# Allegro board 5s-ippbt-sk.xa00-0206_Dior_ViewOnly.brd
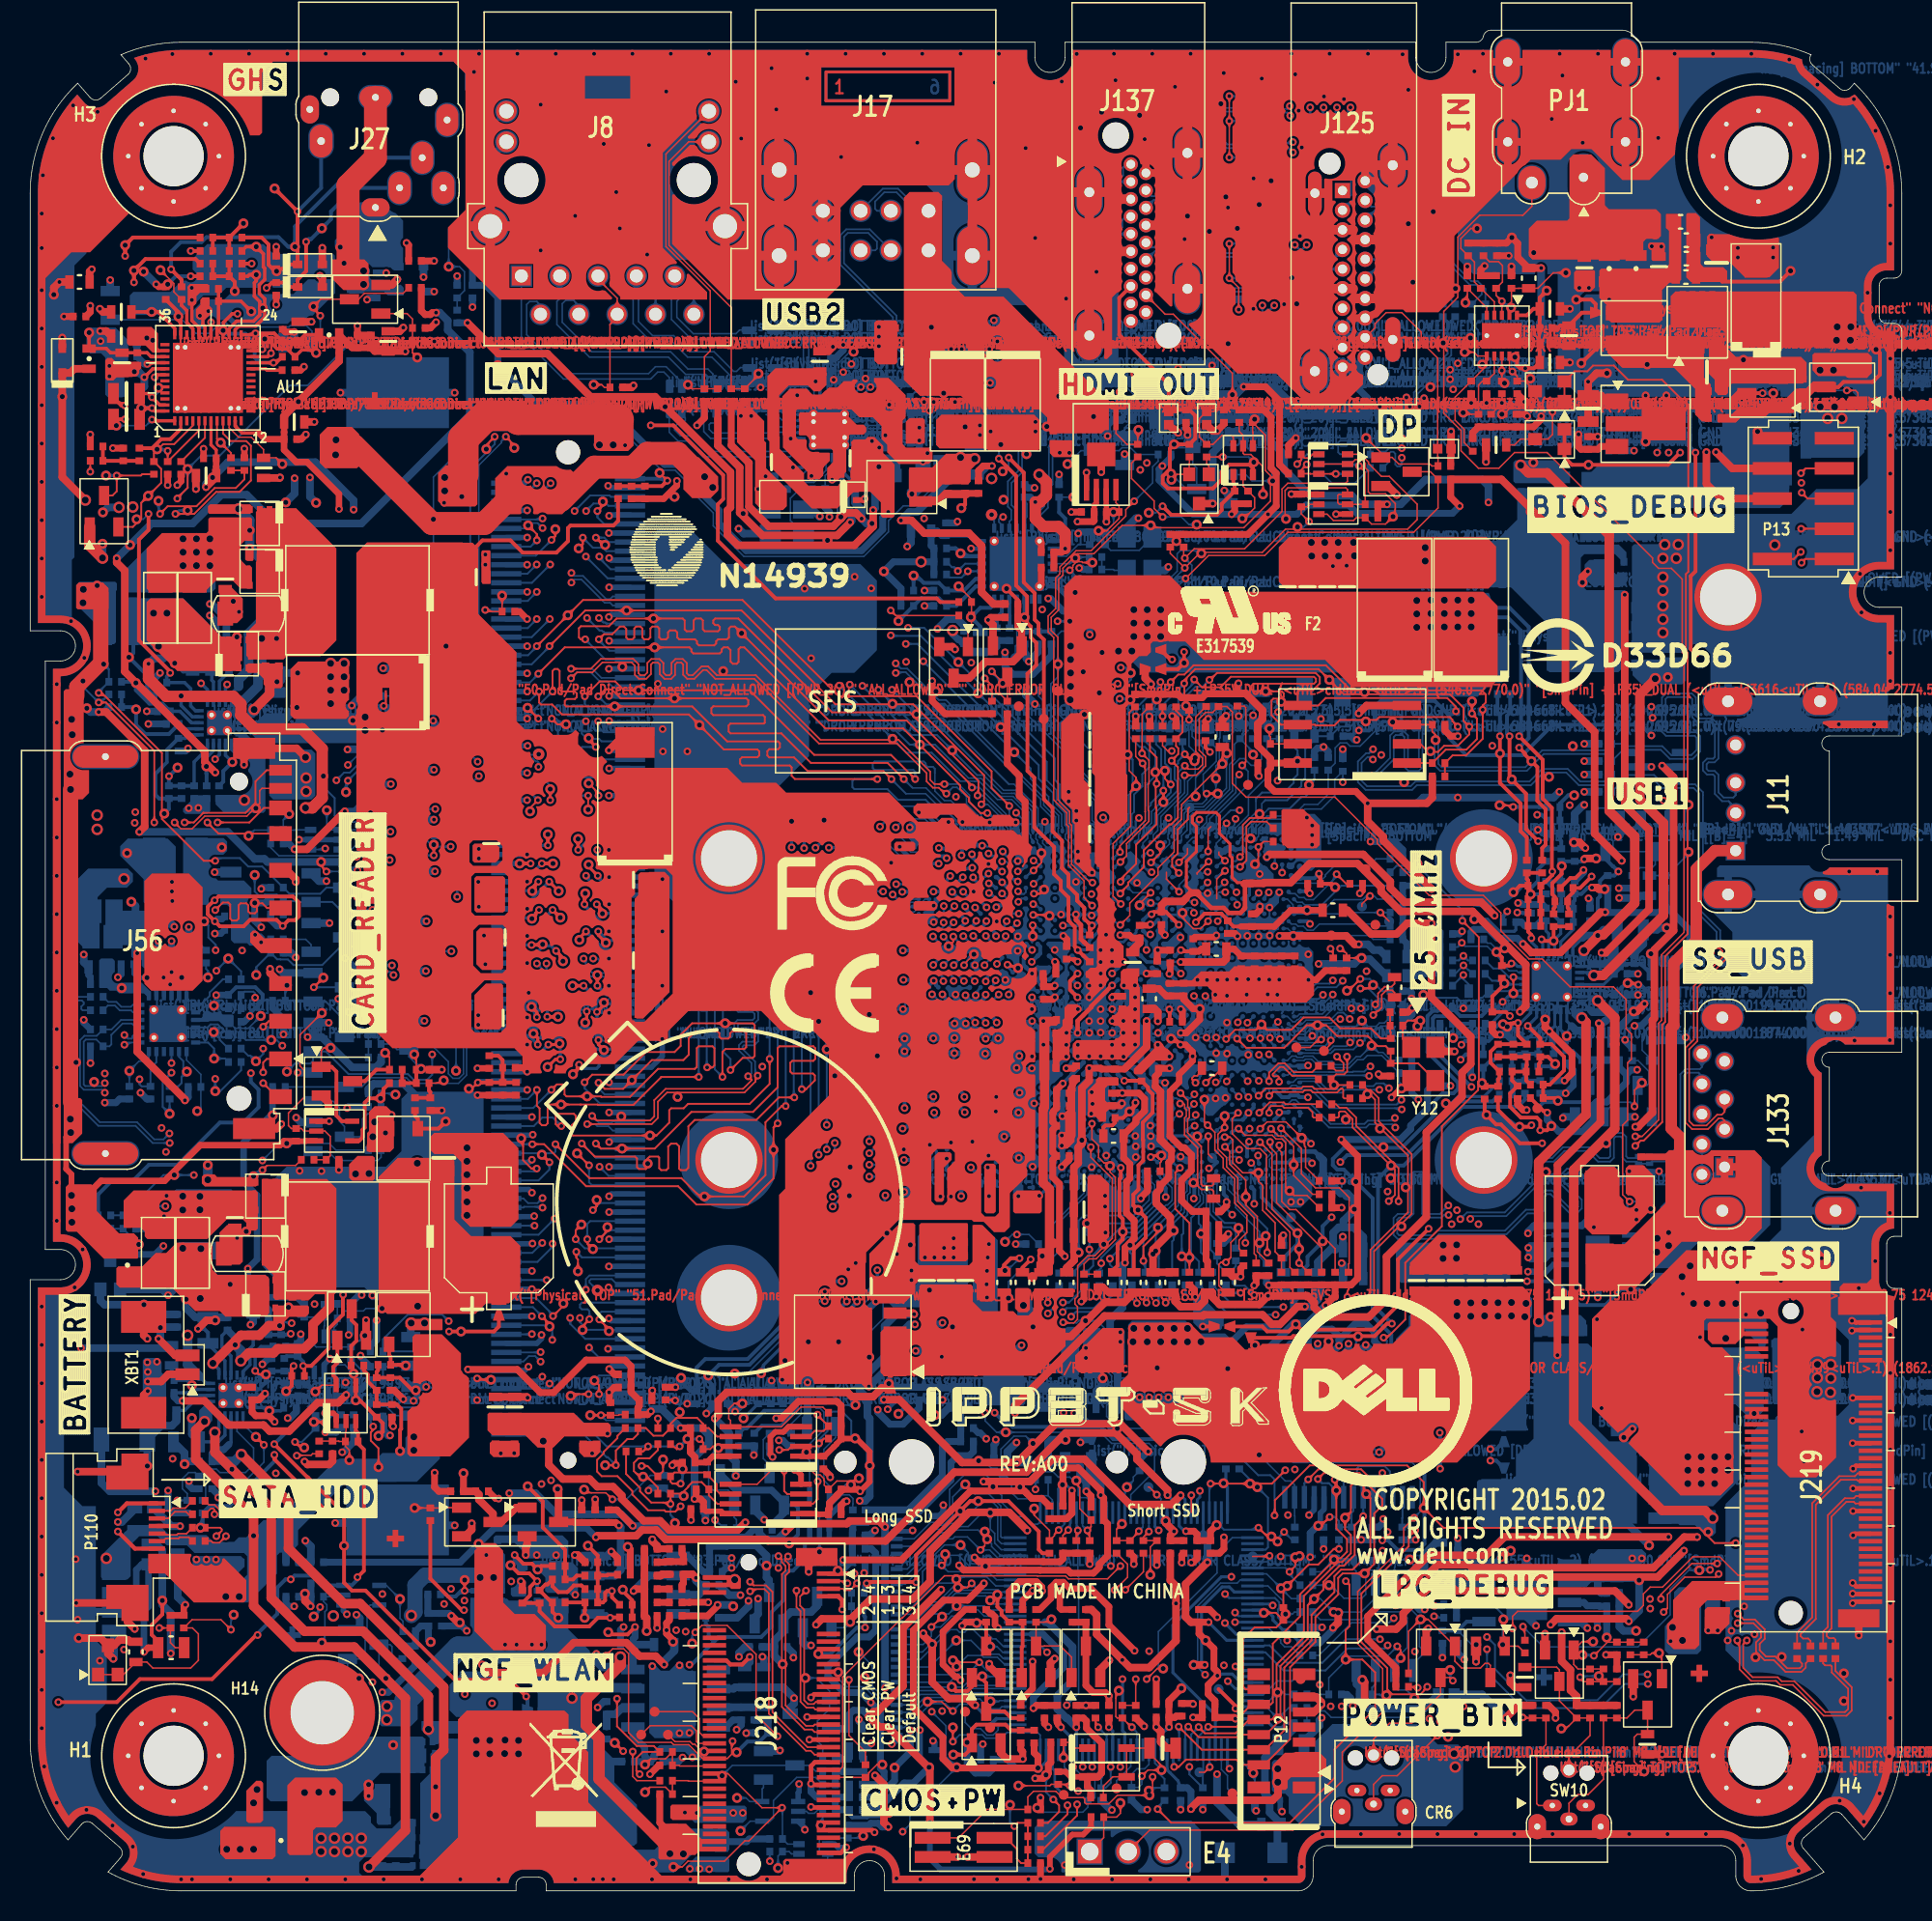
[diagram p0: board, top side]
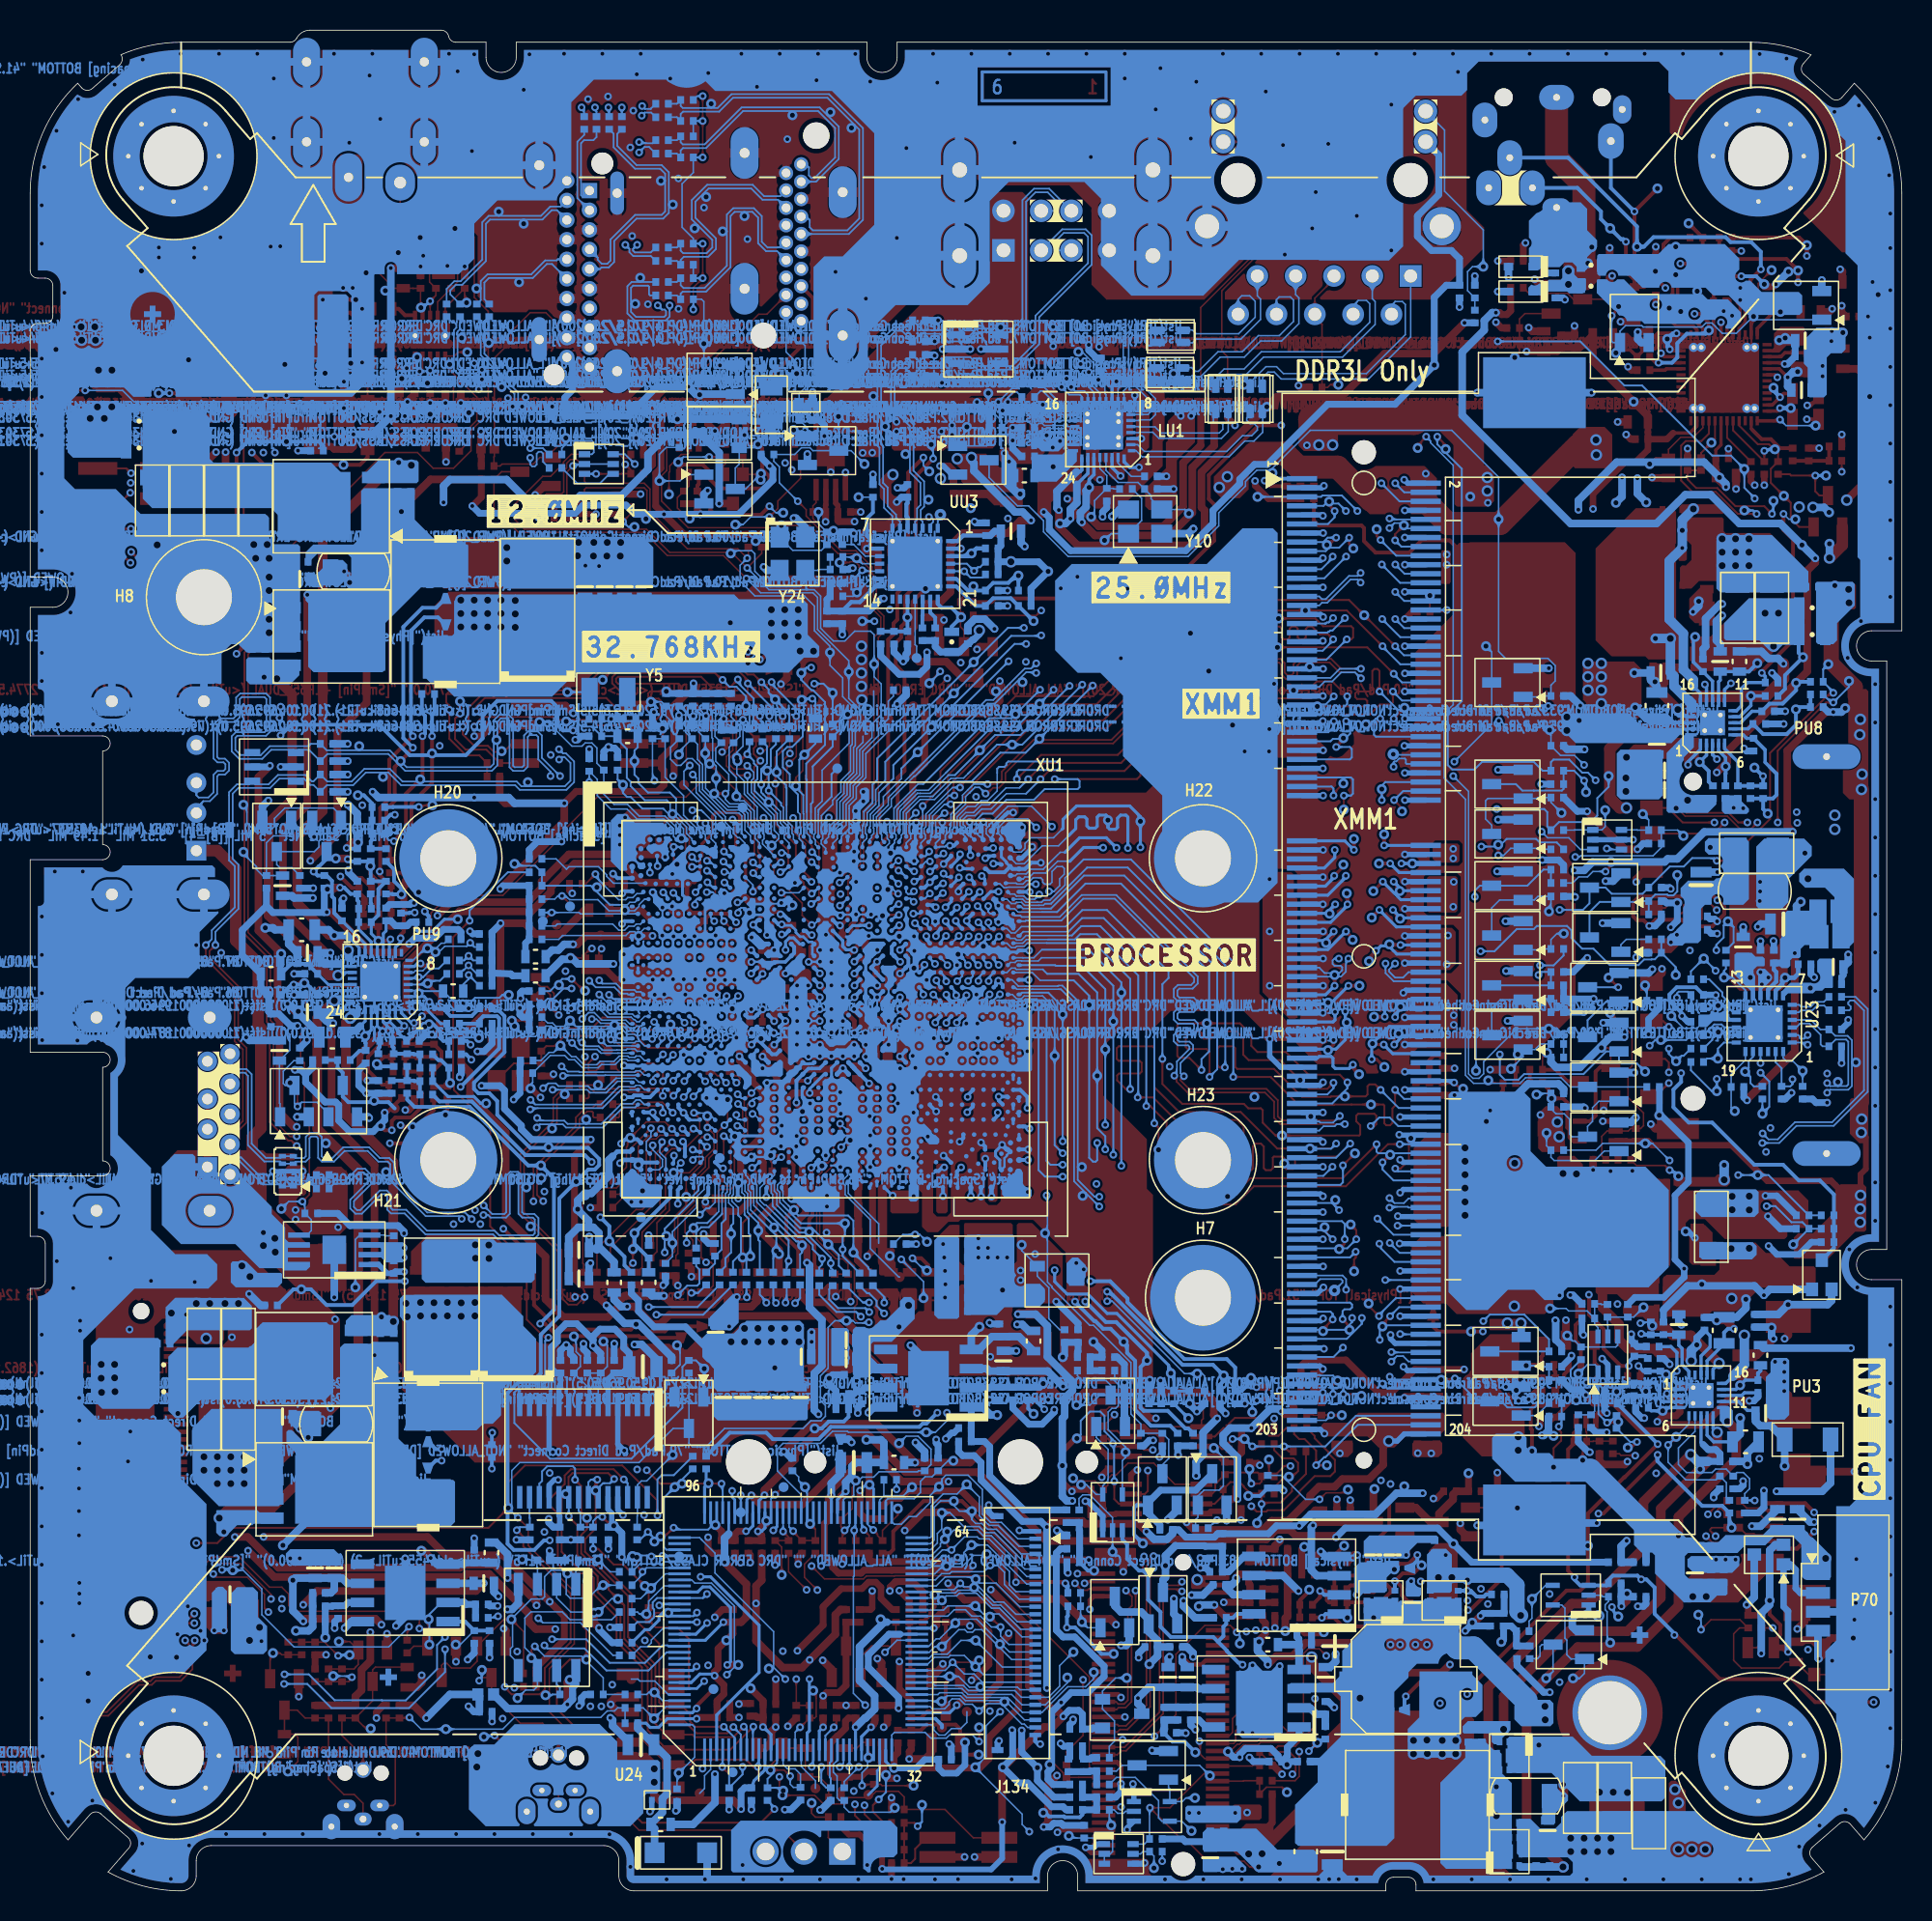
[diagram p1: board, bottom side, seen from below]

Outline 124 x 123.3 mm; copper layers: TOP, VCC, IN1, IN2, GND, BOTTOM. Coordinates in mm from the lower left corner of the outline.
Outline path: 0,112.5 0,83.5 2,83.5 arc(3,82.5) 2,81.5 1,81.5 1,42.5 2,42.5 arc(3,41.5) 2,40.5 0,40.5 0,10 arc(0.65,6.46) 2.51,3.38 3.41,4.42 arc(3.75,4.59) 4.11,4.47 5.93,2.89 arc(6.1,2.55) 5.97,2.19 5.16,1.25 arc(7.5,0.32) 10,0 32.19,0 32.19,0.4 arc(32.33,0.75) 32.69,0.9 33.69,0.9 arc(34.04,0.75) 34.19,0.4 34.19,0 54.6,0 54.6,1 arc(55.6,2) 56.6,1 56.6,0 84,0 arc(84.71,0.29) 85,1 85,2 arc(85.29,2.71) 86,3 112,3 arc(112.71,2.71) 113,2 113,1 arc(113.29,0.29) 114,0 arc(116.5,0.32) 118.84,1.25 117.47,2.83 arc(117.35,3.19) 117.52,3.53 119.33,5.11 arc(119.69,5.23) 120.03,5.06 121.49,3.38 arc(123.35,6.46) 124,10 124,39.92 123.5,39.92 arc(123.15,40.07) 123,40.42 123,42.87 arc(123.15,43.23) 123.5,43.37 124,43.37 124,47.37 119.2,47.37 arc(118.7,47.87) 119.2,48.37 119.2,54.57 arc(118.7,55.07) 119.2,55.57 124,55.57 124,68.33 119.2,68.33 arc(118.7,68.83) 119.2,69.33 119.2,75.53 arc(118.7,76.03) 119.2,76.53 124,76.53 124,85.06 122.5,85.06 arc(121.5,86.06) 122.5,87.06 124,87.06 124,103.37 arc(123.85,103.72) 123.5,103.87 123,103.87 arc(122.65,104.02) 122.5,104.37 122.5,106.37 arc(122.65,106.72) 123,106.87 123.5,106.87 arc(123.85,107.02) 124,107.37 124,112.5 arc(123.18,116.47) 120.85,119.78 120.59,119.48 arc(120.25,119.31) 119.89,119.43 118.07,121.01 arc(117.9,121.32) 117.99,121.67 arc(116.04,122.29) 114,122.5 106.76,122.5 arc(106.52,122.58) 106.35,122.77 arc(105.98,123.16) 105.46,123.3 96.77,123.3 arc(96.45,123.19) 96.28,122.9 arc(96.12,122.62) 95.82,122.5 93.8,122.5 93.8,121.5 arc(92.8,120.5) 91.8,121.5 91.8,122.5 68.56,122.5 68.56,121.5 arc(67.56,120.5) 66.56,121.5 66.56,122.5 10,122.5 arc(7.96,122.29) 6.01,121.67 6.53,121.07 arc(6.65,120.71) 6.48,120.37 4.67,118.79 arc(4.31,118.67) 3.97,118.84 3.15,119.78 arc(0.82,116.47) 0,112.5

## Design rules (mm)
net group HDMI: nets HDMI_TMDS_DATA2_N HDMI_TXN2
net group PCIE_WLAN: nets PCIE_TXP1_WLAN WLAN_PE1_TXP1

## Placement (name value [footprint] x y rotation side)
AC1  -  [MX_C0805_SMALL_T02]  6.38 99.22 180 top
AC2  -  [MX_C0805_SMALL_T02]  6.38 97.51 180 top
AC3  -  [MX_C0402_SMALL_T01]  16.3 107.91 270 top
AC4  -  [MX_C0402_SMALL_T01]  16.3 106.16 90 top
AC5  -  [MX_C0402_SMALL_T01]  22.95 105.98 90 bottom
AC6  -  [MX_C0402_SMALL_T01]  22.95 107.63 90 bottom
AC7  -  [MX_C0402_SMALL_T01]  25.75 103.56 180 top
AC38  -  [MX_C0603_SMALL_T01]  17.49 97.34 0 top
AC39  -  [MX_C0402_SMALL_T01]  17.24 96.2 180 top
AC40  -  [MX_C0603_SMALL_T01]  11.65 93.79 180 top
AC41  -  [MX_C0402_SMALL_T01]  11.9 94.93 0 top
AC42  -  [MX_C0603_SMALL_T01]  6.04 104.63 180 top
AC43  -  [MX_C0402_SMALL_T01]  14.19 94.55 270 top
AC44  -  [MX_C0402_SMALL_T01]  10 94.29 90 top
AC45  -  [MX_C0402_SMALL_T01]  9.11 94.29 90 top
AC46  -  [MX_C0603_SMALL_T01]  15.46 94.29 270 top
AC48  -  [MX_C0603_SMALL_T01]  6.09 101.26 270 top
AC49  -  [MX_C0402_SMALL_T01]  7.1 101.51 90 top
AC50  -  [MX_C0402_SMALL_T01]  3.27 104.33 180 top
AC51  -  [MX_C0402_SMALL_T01]  17.12 101.66 0 top
AC52  -  [MX_C0402_SMALL_T01]  25.49 108.01 0 top
AC53  -  [MX_C0402_SMALL_T01]  21.68 102.68 270 top
AC54  -  [MX_C0603_SMALL_T01]  23.72 102.68 90 top
AC55  -  [MX_C0402_SMALL_T01]  22.57 102.68 270 top
AC56  -  [MX_C0603_SMALL_T01]  17.75 103.31 90 top
AC57  -  [MX_C0402_SMALL_T01]  16.73 103.06 270 top
AC58  -  [MX_C0603_SMALL_T01]  6.04 103.03 180 top
AC59  -  [MX_C0603_SMALL_T01]  6.65 99.45 180 bottom
AC60  -  [MX_C0603_SMALL_T01]  6.4 102.73 180 bottom
AC61  -  [MX_C0402_SMALL_T01]  6.65 101.69 0 bottom
AC62  -  [MX_C0402_SMALL_T01]  17.11 100.77 180 top
AC63  -  [MX_C0402_SMALL_T01]  6.16 95.18 90 top
AD1  -  [MX_SOD523_PHILIPS]  18.53 107.78 0 top
AD2  -  [MX_SOD523_PHILIPS]  18.53 106.28 0 top
AD3  -  [MX_SOD523_PHILIPS]  25.24 105.98 0 bottom
AD4  -  [MX_SOD523_PHILIPS]  25.24 107.63 0 bottom
AQ1  -  [MX_SOT23_H43]  6.34 105.06 180 bottom
AQ2  -  [MX_SOT23_H43]  17.72 103.64 270 bottom
AQ3  -  [MX_SOT23]  22.19 105.47 0 top
AR1  -  [MX_R0402_SMALL_T01]  13.3 94.55 90 top
AR3  -  [MX_R0402_SMALL_T01]  10.03 105.88 90 top
AR5  -  [MX_R0402_SMALL_T01]  12.06 106.16 180 top
AR6  -  [MX_R0402_SMALL]  13.61 109.56 0 top
AR7  -  [MX_R0402_SMALL]  13.61 107.83 0 top
AR8  -  [MX_R0402_SMALL_T01]  25.49 106.23 180 top
AR10  -  [MX_R0402_SMALL_T01]  25.75 102.68 180 top
AR36  -  [MX_R0402_SMALL_T01]  12.06 105.34 180 top
AR37  -  [MX_R0603_SMALL_T01]  3.27 106.61 0 top
AR38  -  [MX_R0402_SMALL_T01]  8.98 105.88 90 top
AU1  -  [MX_QFN_48P_16_S236_PAD_R_8V]  11.78 100.26 0 top
C1  -  [MX_C0402_SMALL]  6.57 43.87 180 bottom
C2  -  [MX_C0402_SMALL_T01]  20.59 31.12 90 bottom
C3  -  [MX_C0402_SMALL_T01]  20.77 37.93 180 bottom
C4  -  [MX_C0402_SMALL_T01]  70.2 89.63 270 bottom
C5  -  [MX_C0402_SMALL_T01]  70.58 87.56 0 bottom
C6  -  [MX_C0402_SMALL_T01]  85.82 51.24 0 top
C7  -  [MX_C0402_SMALL_T01]  85.82 52.13 0 top
C8  -  [MX_C0402_SMALL_T01]  85.77 53.78 180 top
C9  -  [MX_C0402_SMALL_T01]  85.77 54.67 180 top
C10  -  [MX_C0402_SMALL]  64.48 70.42 270 top
C11  -  [MX_C0402_SMALL]  59.53 70.93 270 top
C12  -  [MX_C0402_SMALL]  58.89 65.72 90 top
C13  -  [MX_C0402_SMALL]  63.09 45.27 180 top
C14  -  [MX_C0402_SMALL_T01]  68.67 62.16 270 top
C15  -  [MX_C0402_SMALL_T01]  83.02 42.35 270 bottom
C16  -  [MX_C0402_SMALL_T01]  67.53 56.83 180 top
C17  -  [MX_C0402_SMALL_T01]  67.53 55.43 180 top
C18  -  [MX_C0402_SMALL_T01]  67.53 54.54 180 top
C19  -  [MX_C0402_SMALL_T01]  68.42 57.72 180 top
C20  -  [MX_C0402_SMALL_T01]  78.33 44.13 180 top
C21  -  [MX_C0402_SMALL_T01]  78.33 42.35 180 top
C22  -  [MX_C0402_SMALL_T01]  82.01 61.53 90 top
C23  -  [MX_C0402_SMALL_T01]  82.9 61.53 90 top
C24  -  [MX_C0402_SMALL_T01]  83.79 61.53 90 top
C25  -  [MX_C0402_SMALL_T01]  81.12 61.53 90 top
C26  -  [MX_C0402_SMALL_T01]  80.23 61.53 90 top
C27  -  [MX_C0402_SMALL_T01]  67.15 59.5 90 top
C28  -  [MX_C0402_SMALL_T01]  73.5 63.56 90 top
C30  -  [MX_C0402_SMALL_T01]  75.53 61.91 270 top
C31  -  [MX_C0402_SMALL_T01]  60.67 47.68 0 top
C32  -  [MX_C0402_SMALL_T01]  64.99 45.27 180 top
C33  -  [MX_C0402_SMALL_T01]  58.26 68.77 270 top
C34  -  [MX_C0402_SMALL_T01]  63.09 47.05 180 top
C35  -  [MX_C0402_SMALL_T01]  60.67 46.8 0 top
C36  -  [MX_C0402_SMALL_T01]  62.58 70.42 270 top
C37  -  [MX_C0402_SMALL_T01]  71.85 54.03 90 top
C38  -  [MX_C0402_SMALL_T01]  74.67 61.2 270 top
C39  -  [MX_C0603_SMALL_T02]  69.82 43.43 0 top
C40  -  [MX_C0603_SMALL_T02]  69.82 45.14 0 top
C41  -  [MX_C0603_SMALL_T02]  69.82 46.92 0 top
C42  -  [MX_C0402_SMALL_T01]  75.91 57.59 180 top
C43  -  [MX_C0402_SMALL_T01]  85.06 66.73 0 top
C44  -  [MX_C0402_SMALL_T01]  74.77 54.92 270 top
C45  -  [MX_C0402_SMALL_T01]  79.34 63.86 90 top
C46  -  [MX_C0402_SMALL_T01]  80.95 64.32 270 top
C47  -  [MX_C0402_SMALL_T01]  73.63 54.09 270 top
C48  -  [MX_C0402_SMALL_T01]  62.32 42.99 180 top
C49  -  [MX_C0402_SMALL_T01]  62.32 42.1 180 top
C50  -  [MX_C0402_SMALL_T01]  58.77 43.87 0 top
C51  -  [MX_C0402_SMALL_T01]  62.32 39.3 180 bottom
C52  -  [MX_C0402_SMALL_T01]  62.32 43.87 180 top
C53  -  [MX_C0402_SMALL_T01]  62.32 38.41 180 bottom
C54  -  [MX_C0402_SMALL_T01]  62.32 40.19 180 bottom
C55  -  [MX_C0402_SMALL_T01]  62.32 41.97 180 bottom
C56  -  [MX_C0603_SMALL_T01]  75.53 32.7 270 bottom
C57  -  [MX_C0603_SMALL_T01]  78.07 32.7 270 bottom
C58  -  [MX_C0603_SMALL_T01]  76.8 32.7 270 bottom
C59  -  [MX_C0603_SMALL_T01]  73.04 61.53 90 top
C60  -  [MX_C0603_SMALL_T01]  72.99 32.7 270 bottom
C61  -  [MX_C0603_SMALL_T01]  74.26 32.7 270 bottom
C62  -  [MX_C0402_SMALL_T01]  75.53 59.72 270 top
C63  -  [MX_C0402_SMALL_T01]  76.42 59.72 270 top
C64  -  [MX_C0603_SMALL_T02]  87.65 42.47 180 bottom
C65  -  [MX_C0603_SMALL_T01]  87.65 40.57 180 bottom
C66  -  [MX_C0402_SMALL_T01]  74.44 46.8 0 top
C67  -  [MX_C0402_SMALL_T01]  77.87 76.64 270 top
C68  -  [MX_C0402_SMALL_T01]  74.95 64.45 90 top
C69  -  [MX_C0402_SMALL_T01]  71.67 52.43 90 top
C70  -  [MX_C0402_SMALL_T01]  71.46 51.22 0 top
C71  -  [MX_C0402_SMALL_T01]  68.42 52.87 180 top
C72  -  [MX_C0402_SMALL_T01]  68.42 52 180 top
C73  -  [MX_C0402_SMALL_T01]  68.42 50.69 180 top
C74  -  [MX_C0402_SMALL_T01]  68.42 48.7 180 top
C75  -  [MX_C0402_SMALL_T01]  69.3 54.25 90 top
C76  -  [MX_C0402_SMALL_T01]  72.36 58.86 270 top
C77  -  [MX_C0402_SMALL_T01]  72.61 34.73 0 top
C78  -  [MX_C0402_SMALL_T01]  72.61 35.62 0 top
C79  -  [MX_C0603_SMALL_T02]  70.2 73.72 180 top
C80  -  [MX_C0603_SMALL_T02]  70.2 76.26 180 top
C81  -  [MX_C0603_SMALL_T02]  70.2 77.53 180 top
C82  -  [MX_C0603_SMALL_T01]  70.2 74.99 180 top
C83  -  [MX_C0402_SMALL]  70.48 69 0 top
C84  -  [MX_C0402_SMALL]  70.48 68.11 0 top
C85  -  [MX_C0603_SMALL_T01]  70.2 72.45 180 top
C86  -  [MX_C0603_SMALL_T01]  70.2 70.04 180 top
C89  -  [MX_C0402_SMALL]  30.42 54.92 90 top
C149  -  [MX_C0402_SMALL_T01]  66.51 5.39 180 top
C150  -  [MX_C0402_SMALL_T01]  66.51 1.84 180 top
C151  -  [MX_C0402_SMALL_T01]  54.15 93.89 0 top
C152  -  [MX_C0402_SMALL_T01]  48.86 95.69 0 top
C153  -  [MX_C0603_SMALL_T01]  52.32 101.36 90 top
C154  -  [MX_C0402_SMALL]  55.03 96.35 270 top
C155  -  [MX_C0402_SMALL_T01]  52.67 95.44 270 top
C156  -  [MX_C0402_SMALL_T01]  57.88 96.2 180 top
C157  -  [MX_C0402_SMALL_T01]  51.17 98.05 90 top
C158  -  [MX_C0402_SMALL_T01]  51.17 96.28 270 top
C159  -  [MX_C0402_SMALL_T01]  57.88 97.09 180 top
C160  -  [MX_C0402_SMALL_T01]  57.88 95.06 180 bottom
C161  -  [MX_C0402_SMALL_T01]  57.88 99.88 180 bottom
C162  -  [MX_C0402_SMALL_T01]  57.88 98.99 180 bottom
C163  -  [MX_C0402_SMALL_T01]  57.88 97.98 180 bottom
C174  -  [MX_C0402_SMALL_T01]  7.23 95.18 270 top
C240  -  [MX_C0402_SMALL]  6.57 44.76 180 bottom
C245  -  [MX_C0402_SMALL_T01]  13.3 64.58 0 bottom
C246  -  [MX_C0805_SMALL_T02]  13.3 66.64 90 bottom
C248  -  [MX_C0402_SMALL]  13.56 59.37 0 bottom
C249  -  [MX_C0402_SMALL_T01]  13.3 63.69 0 bottom
C250  -  [MX_C0402_SMALL_T01]  4.41 55.97 0 bottom
C251  -  [MX_C0402_SMALL_T01]  4.41 57.08 0 bottom
C252  -  [MX_C0603_SMALL_T01]  4.54 61.22 180 bottom
C253  -  [MX_C0402_SMALL_T01]  4.41 60.08 0 bottom
C254  -  [MX_C0402_SMALL]  13.56 57.59 180 bottom
C255  -  [MX_C0603_SMALL_T01]  10.51 62.54 90 bottom
C256  -  [MX_C0402_SMALL_T01]  9.36 61.91 270 bottom
C257  -  [MX_C0402_SMALL_T01]  8.48 61.91 270 bottom
C260  -  [MX_C0805_SMALL_T02]  83.53 9.69 0 bottom
C261  -  [MX_C0402_SMALL_T01]  78.07 12.38 0 top
C262  -  [MX_C0402_SMALL_T01]  78.07 11.49 0 top
C263  -  [MX_C0402_SMALL_T01]  77.44 18.22 270 top
C264  -  [MX_C0402_SMALL_T01]  69.31 11.87 270 top
C265  -  [MX_C0805_SMALL_T02]  69.44 28.38 0 bottom
C266  -  [MX_C0402_SMALL_T01]  70.71 25.46 180 top
C267  -  [MX_C0402_SMALL_T01]  76.22 6.41 90 bottom
C268  -  [MX_C0402_SMALL_T01]  75.02 12.38 0 top
C269  -  [MX_C0402_SMALL]  76.29 12 270 top
C272  -  [MX_C0402_SMALL_T01]  93.82 11.87 0 bottom
C302  -  [MX_C0402_SMALL_T01]  7.97 52.89 270 bottom
C307  -  [MX_C0603_SMALL_T01]  49.12 94.67 180 top
C308  -  [MX_C0603_SMALL_T01]  54.32 94.93 180 top
C941134  -  [MX_C0402_SMALL_T01]  78.33 45.02 180 top
C941135  -  [MX_C0402_SMALL_T01]  78.33 43.24 180 top
C941136  -  [MX_C0402_SMALL_T01]  67.53 60.77 180 top
C941137  -  [MX_C0402_SMALL_T01]  77.06 62.67 270 top
C941138  -  [MX_C0402_SMALL_T01]  62.32 42.86 180 bottom
C941139  -  [MX_C0402_SMALL_T01]  62.32 41.08 180 bottom
C941140  -  [MX_C0402_SMALL_T01]  39.84 58.1 180 top
C941141  -  [MX_C0402_SMALL_T01]  39.84 59.88 180 top
C941156  -  [MX_C0402_SMALL_T01]  67.78 96.33 90 top
C941162  -  [MX_C0402_SMALL_T01]  82.77 76.77 270 bottom
C941163  -  [MX_C0402_SMALL_T01]  75.91 76.77 270 top
CB1  -  [MX_C0805_SMALL]  83.41 34.73 0 bottom
CB2  -  [MX_C0402_SMALL_T01]  87.55 23.68 90 bottom
CB3  -  [MX_C0402_SMALL_T01]  90.9 23.68 90 bottom
CB6  -  [MX_C0402_SMALL_T01]  99.92 41.33 90 bottom
CB7  -  [MX_C0402_SMALL_T01]  107.66 41.08 90 bottom
CB10  -  [MX_C0603_SMALL]  107.15 9.71 270 top
CB12  -  [MX_C0603_SMALL]  99.03 14.16 270 top
CE4118  -  [MX_C3528]  65.12 98.48 90 top
CE4119  -  [MX_C3528]  61.43 98.48 90 top
CR6  -  [MX_TP_SW_4P_4HOLD_DIPTRON]  89 8.8 0 top
D1  -  [MX_SOT23_H43]  4.89 91.42 270 top
D2  -  [MX_SOD123]  51.02 92.39 180 top
D3  -  [MX_S0402_AMAZ]  54.7 92.52 270 top
D3C1  -  [MX_C0402_SMALL_T01]  31.69 84.77 180 top
D3CB1  -  [MX_C0402_SMALL_T01]  32.19 53.15 90 top
D3CB2  -  [MX_C0402_SMALL_T01]  39.84 92.67 270 top
D3CB5  -  [MX_C0402_SMALL_T01]  31.3 53.15 90 top
D3CB6  -  [MX_C0402_SMALL_T01]  39.39 33.36 0 top
D3CB7  -  [MX_C0402_SMALL_T01]  39.39 34.22 0 top
D3CB8  -  [MX_C0402_SMALL_T01]  40.77 32.51 180 top
D3R1  -  [MX_R0402_SMALL_T01]  38.95 92.67 90 top
D3R2  -  [MX_R0402_SMALL_T01]  31.72 54.54 180 top
D3R3  -  [MX_R0402_SMALL_T01]  40.73 92.67 270 top
D3R4  -  [MX_R0402_SMALL_T01]  30.42 53.15 270 top
D4  -  [MX_SOD523]  2.13 101.41 90 top
D28  -  [MX_SOD323_H37]  71.34 7.55 0 top
D29  -  [MX_SOD323_H37]  71.34 9.46 0 top
D32  -  [MX_S0402_AMAZ]  82.47 6.03 0 bottom
D33  -  [MX_SOD123]  80.89 2.52 180 bottom
DCB1  -  [MX_C0603_SMALL_T01]  32.1 32.06 90 top
DCB3  -  [MX_C0402_SMALL_T01]  37.53 30.03 90 top
DCB4  -  [MX_C0402_SMALL_T01]  30.83 30.03 90 top
DCB5  -  [MX_C0402_SMALL_T01]  32.1 30.03 90 top
DCB6  -  [MX_C0402_SMALL_T01]  36.64 30.03 90 top
DCB7  -  [MX_C0603_SMALL_T01]  39.97 66.99 0 top
DCB15  -  [MX_C0402_SMALL_T01]  39.84 63.56 180 top
DCB16  -  [MX_C0402_SMALL_T01]  31.46 61.4 0 top
DCB17  -  [MX_C0402_SMALL_T01]  31.46 59.75 0 top
DCB18  -  [MX_C0402_SMALL_T01]  39.84 65.21 180 top
DCB19  -  [MX_C0402_SMALL_T01]  31.58 66.86 0 top
DCB20  -  [MX_C0402_SMALL_T01]  31.59 65.21 0 top
DCB21  -  [MX_C0603_SMALL_T01]  30.83 32.06 90 top
DCB22  -  [MX_C0603_SMALL_T01]  39.97 61.65 0 top
DCB23  -  [MX_C0603_SMALL_T01]  31.46 63.18 180 top
DCB24  -  [MX_C0603_SMALL_T01]  30.55 69.4 270 top
DCB25  -  [MX_C0603_SMALL_T01]  31.34 57.84 180 top
DEC1  -  [MX_C0402_SMALL_T01]  60.67 90.23 270 bottom
DEC2  -  [MX_C0603_SMALL_T01]  59.02 90.1 180 bottom
DEC3  -  [MX_C0402_SMALL_T01]  61.88 83.07 270 bottom
DEC4  -  [MX_C0402_SMALL_T01]  65.88 83.04 90 bottom
DEC5  -  [MX_C0402_SMALL_T01]  65.88 92.77 270 bottom
DEC6  -  [MX_C0402_SMALL_T01]  67.4 87.69 0 top
DEC7  -  [MX_C0402_SMALL_T01]  67.4 88.71 0 top
DEC8  -  [MX_C0402_SMALL_T01]  70.2 84.39 90 bottom
DEC9  -  [MX_C0402_SMALL_T01]  71.21 84.39 90 bottom
E4  -  [MX_HD_1X3P_100_LF3]  72.74 2.6 0 top
E69  -  [MX_HD_2X2P_50_JV]  61.84 2.88 270 top
F3  -  [MX_POLYSWITCH_2P_126X62_H28]  9.62 68.77 0 bottom
F3R1  -  [MX_R0402_SMALL_T01]  93.31 73.85 0 top
F3R2  -  [MX_R0402_SMALL_T01]  93.31 77.28 180 top
F3R3  -  [MX_R0402_SMALL_T01]  81.75 76.01 0 top
F3U1  -  [MX_SOIC_8P_50_213X311]  87.6 76.64 90 top
FC1  -  [MX_C0402_SMALL_T01]  81.75 74.74 0 top
FC2  -  [MX_C0603_SMALL_T02]  6.93 24.62 90 bottom
FC3  -  [MX_C0603_SMALL_T02]  8.23 24.62 90 bottom
FD3  -  [MX_SOT323]  8.81 22.28 180 bottom
FD4  -  [MX_SOT323]  5.15 15.3 270 top
FD5  -  [MX_SOT323]  77.44 92.9 90 top
FR1  -  [MX_R0402_SMALL_T01]  9.29 17.84 270 top
FR3  -  [MX_R0805_SMALL_T02]  9.34 16.11 180 top
FR4  -  [MX_R0603_SMALL_T01]  7 15.83 270 top
FR5  -  [MX_R0402_SMALL_T01]  10.18 17.84 270 top
H1  -  [MX_HOLEC315D157N_M2P2V8]  9.5 8.95 180 top
H2  -  [MX_HOLEC315D157N_M2P2V8]  114.5 114.95 180 top
H3  -  [MX_HOLEC315D157N_M2P2V8]  9.5 114.95 180 top
H4  -  [MX_HOLEC315D157N_M2P2V8]  114.5 8.95 180 top
H6  -  [MX_HOLE_C59D59N]  72.01 28.42 0 top
H7  -  [SMT_NUT_CT276B176D146_H220]  46.3 39.3 180 bottom
H8  -  [SMT_NUT_CT276B176D146_H220]  112.49 85.73 180 bottom
H9  -  [MX_HOLE_C118D118N]  76.41 28.42 0 top
H10  -  [MX_HOLE_C118D118N]  58.4 28.42 0 top
H11  -  [MX_HOLE_C59D59N]  54 28.42 0 top
H14  -  [MX_SMT_NUT_CT276B195D165]  19.35 11.8 0 top
H20  -  [MX_NUT_CT256BD146_H71]  96.3 68.43 180 bottom
H21  -  [MX_NUT_CT256BD146_H71]  96.3 48.43 180 bottom
H22  -  [MX_NUT_CT256BD146_H71]  46.3 68.43 180 bottom
H23  -  [MX_NUT_CT256BD146_H71]  46.3 48.43 180 bottom
HC1  -  [MX_C0402_SMALL_T01]  63.72 78.42 90 top
HC2  -  [MX_C0402_SMALL_T01]  47.21 32.7 90 bottom
HC9  -  [MX_C0402_SMALL_T01]  65.02 84.39 0 top
HC10  -  [MX_C0402_SMALL_T01]  48.99 29.9 90 bottom
HC11  -  [MX_C0402_SMALL_T01]  84.55 17.46 180 bottom
HC12  -  [MX_C0402_SMALL_T01]  70.58 11.87 270 top
HC13  -  [MX_C0402_SMALL_T01]  78.63 42.48 270 bottom
HC14  -  [MX_C0402_SMALL_T01]  77.69 6.41 90 bottom
HR1  -  [MX_R0402_SMALL_T01]  13.61 108.67 180 top
HR2  -  [MX_R0402_SMALL_T01]  13.61 106.99 180 top
HR3  -  [MX_R0402_SMALL_T01]  11.68 106.99 180 top
HR4  -  [MX_R0402_SMALL_T01]  11.68 108.67 180 top
HUBL1  -  [MX_L0603_SMALL_T02]  62.95 82.76 90 bottom
J8  -  [LAN_CON_14P_4HLD_S_UDE_LF5]  38.25 113.36 180 top
J11  -  [USB_1X4P_4HD_RA_JYEC_LF3]  118.59 72.43 90 top
J17  -  [MX_USB_2X4P_4H_RA_VIT_LF5]  56.02 114.04 180 top
J27  -  [MX_PHONE_JACK_6P_4HD_SG_LF5]  22.87 118.85 180 top
J56  -  [SD_CARD_9P_8HOLD_PLA_LF3]  13.84 62.01 270 top
J125  -  [T_DISPLAY_20P_26_6H_RA_LF3]  87.69 107.47 180 top
J133  -  [USB_9P_4HOLD_RA_JYEC_LF5]  119.61 51.47 90 top
J134  -  [FPC_26P_20_4HD_RA_PANASONIC]  59.91 17.08 270 bottom
J137  -  [MX_HDMI_CON_19P_6H_SING_LF3]  73.67 109.69 180 top
J218  -  [MX_MINI_PCI_67P_4HD_COLAY]  47.61 11.77 270 top
J219  -  [MX_MINI_PCI_67P_20_4HD_H165]  116.65 28.41 270 top
JP4  -  [SHORTPIN]  70.32 29.4 270 bottom
L1  -  [MX_L0603_SMALL]  3.9 101.53 90 top
L2  -  [MX_L0603_SMALL]  19.8 103.11 180 top
L3  -  [MX_L0603_SMALL]  20.59 106.33 0 bottom
L4  -  [MX_L0603_SMALL]  20.59 107.73 0 bottom
LANC1  -  [MX_C0402_SMALL_T01]  28.29 105.98 270 bottom
LANC3  -  [MX_C0402_SMALL_T01]  47.34 99.12 90 top
LANC4  -  [MX_C0402_SMALL_T01]  44.67 99.12 90 top
LC1  -  [MX_C0402_SMALL_T01]  52.67 92.52 90 bottom
LC2  -  [MX_C0402_SMALL_T01]  49.75 92.9 0 bottom
LC16  -  [MX_C0402_SMALL_T01]  38.83 99.63 180 top
LC17  -  [MX_C0402_SMALL_T01]  29.3 105.98 90 bottom
LL10  -  [MX_CHOKE_4P_79X47_FUKUI]  42.77 98.87 90 bottom
LL11  -  [MX_CHOKE_4P_79X47_FUKUI]  45.05 98.87 90 bottom
LL12  -  [MX_CHOKE_4P_79X47_FUKUI]  48.48 100.52 180 bottom
LL13  -  [MX_CHOKE_4P_79X47_FUKUI]  48.43 103.01 180 bottom
LQ3  -  [MX_SOT23]  61.51 94.8 0 bottom
LR1  -  [MX_R0402_SMALL_T01]  51.4 92.9 180 bottom
LR2  -  [MX_R0402_SMALL_T01]  49.75 93.74 180 bottom
LR62  -  [MX_R0402_SMALL_T01]  28.29 104.33 270 bottom
LR85  -  [MX_R0402_SMALL_T01]  45.56 99.12 90 top
LR87  -  [MX_R0402_SMALL_T01]  46.45 99.12 90 top
LRN11  -  [MX_2R4P0603]  42.77 98.87 0 bottom
LRN12  -  [MX_2R4P0603]  45.05 98.87 0 bottom
LRN13  -  [MX_2R4P0603]  48.48 100.52 90 bottom
LRN14  -  [MX_2R4P0603]  48.43 103.01 90 bottom
LU1  -  [MX_QFN_32P_16_S157_P_H39_8V]  52.93 96.83 90 bottom
M1C1  -  [MX_C0402_SMALL_T01]  82.14 117.53 0 bottom
M1C2  -  [MX_C0402_SMALL_T01]  82.14 118.42 0 bottom
M1C3  -  [MX_C0402_SMALL_T01]  82.14 108.9 0 bottom
M1C4  -  [MX_C0402_SMALL_T01]  82.14 108.01 0 bottom
M1C5  -  [MX_C0402_SMALL_T01]  82.14 115.12 0 bottom
M1C6  -  [MX_C0402_SMALL_T01]  82.14 116.01 0 bottom
M1C7  -  [MX_C0402_SMALL_T01]  82.14 106.61 0 bottom
M1C8  -  [MX_C0402_SMALL_T01]  82.14 105.72 0 bottom
M1C9  -  [MX_C0402_SMALL_T01]  79.09 97.72 90 top
M1C10  -  [MX_C0402_SMALL_T01]  76.57 97.72 90 top
M1C11  -  [MX_C0402_SMALL_T01]  86.48 117.15 90 bottom
M1C12  -  [MX_C0402_SMALL_T01]  96.41 104.73 270 bottom
M1C13  -  [MX_C0402_SMALL_T01]  87.29 117.15 90 bottom
M1C14  -  [MX_C0402_SMALL_T01]  88.99 97.72 180 bottom
M1C15  -  [MX_C0402_SMALL_T01]  95.52 104.73 270 bottom
M1C16  -  [MX_C0402_SMALL_T01]  85.64 117.15 90 bottom
M1C17  -  [MX_C0402_SMALL_T01]  84.8 117.15 90 bottom
M1C18  -  [MX_C0402_SMALL_T01]  94.41 104.73 270 bottom
M1C19  -  [MX_C0402_SMALL_T01]  93.59 104.73 270 bottom
M1C20  -  [MX_C0402_SMALL_T01]  89.2 95.18 0 bottom
M1C21  -  [MX_C0402_SMALL_T01]  89.2 94.29 0 bottom
M1R1  -  [MX_R0402_SMALL_T01]  83.79 93.91 0 top
M1R2  -  [MX_R0402_SMALL_T01]  83.79 95.18 180 top
MCB1  -  [MX_C0402_SMALL_T01]  75.02 100.9 180 bottom
MD1  -  [MX_S0402_AMAZ_COLAY]  72.61 98.61 180 bottom
MD2  -  [MX_S0402_AMAZ_COLAY]  77.94 97.6 270 top
MD3  -  [MX_S0402_AMAZ_COLAY]  75.43 97.6 270 top
MD5  -  [MX_S0402_AMAZ_COLAY]  93.69 95.56 0 top
MQ1  -  [MX_SOT23_H43]  71.47 95.44 0 bottom
MQ3  -  [MX_SOT23_H43]  90.52 94.04 180 top
MQ5  -  [MX_SOT23]  26.13 70.04 180 bottom
MQ6  -  [MX_SOT23_H43]  26.26 35.75 180 bottom
MQ7  -  [MX_SOT23]  26.26 32.44 180 bottom
MQ8  -  [MX_SOT23_H43]  19.65 66.48 180 bottom
MQ9  -  [MX_SOT23]  19.65 63.18 180 bottom
MQ22  -  [MX_SOT23_H43]  26.13 60 180 bottom
MQ23  -  [MX_SOT23]  26.13 56.7 180 bottom
MQ25  -  [MX_SOT23_H43]  26.13 66.61 180 bottom
MQ31  -  [MX_SOT23_H43]  19.78 53.27 180 bottom
MQ32  -  [MX_SOT23]  19.78 49.97 180 bottom
MQ33  -  [MX_SOT23_2D4_H51]  78.33 96.58 90 bottom
MQ34  -  [MX_SOT23_H43_COLAY]  78.33 92.9 0 bottom
MQ36  -  [MX_SOT23_H43_COLAY]  78.33 100.14 180 bottom
MQ37  -  [MX_SOT363]  80.36 94.8 0 top
MQ40  -  [MX_SOT363]  86.33 94.55 270 top
MQ41  -  [MX_SOT363]  86.33 91.88 270 top
MQ42  -  [MX_SOT363]  86.33 94.55 270 bottom
MR1  -  [MX_R0402_SMALL_T01]  80.99 96.07 270 bottom
MR2  -  [MX_R0402_SMALL_T01]  75.15 96.07 0 bottom
MR6  -  [MX_R0402_SMALL_T01]  80.48 117.28 180 bottom
MR7  -  [MX_R0402_SMALL_T01]  80.48 118.68 180 bottom
MR8  -  [MX_R0402_SMALL_T01]  80.48 109.15 180 bottom
MR9  -  [MX_R0402_SMALL_T01]  80.48 107.76 180 bottom
MR10  -  [MX_R0402_SMALL_T01]  80.48 114.87 180 bottom
MR11  -  [MX_R0402_SMALL_T01]  80.48 116.26 180 bottom
MR12  -  [MX_R0402_SMALL_T01]  80.48 106.87 180 bottom
MR13  -  [MX_R0402_SMALL_T01]  80.48 105.47 180 bottom
MR14  -  [MX_R0402_SMALL_T01]  80.99 97.72 270 top
MR15  -  [MX_R0402_SMALL_T01]  79.8 92.34 90 top
MR16  -  [MX_R0402_SMALL_T01]  80.1 97.72 270 top
MR17  -  [MX_R0402_SMALL_T01]  80.69 92.34 90 top
MR18  -  [MX_R0402_SMALL_T01]  77.94 95.44 90 top
MR19  -  [MX_R0402_SMALL_T01]  76.8 95.44 90 top
MR24  -  [MX_R0402_SMALL_T01]  88.87 90.99 180 top
MR25  -  [MX_R0402_SMALL_T01]  88.87 91.88 180 top
MR26  -  [MX_R0402_SMALL_T01]  84.21 92.13 270 top
NOREF  -  []  14.37 120.07 0 top
NOREF#2  -  []  92.68 11.49 0 top
NOREF#3  -  []  62.05 32.25 0 top
NOREF#4  -  []  60.32 5.93 0 top
NOREF#5  -  []  75.71 30.81 0 top
NOREF#6  -  []  70.62 30.84 0 top
NOREF#7  -  []  48.61 56.45 0 top
NOREF#8  -  []  59.38 30.84 0 top
NOREF#9  -  []  51.32 104.39 0 top
NOREF#10  -  []  42.26 88.76 0 top
NOREF#11  -  []  32.16 100.28 0 top
NOREF#12  -  [unnamed#2]  22.83 98.74 0 top
NOREF#13  -  []  114.53 61.89 0 top
NOREF#14  -  []  65.22 32.25 0 top
NOREF#15  -  []  90.74 96.93 0 top
NOREF#16  -  []  115.25 42.16 0 top
NOREF#17  -  [unnamed#2]  24.2 23.35 0 top
NOREF#18  -  []  73.69 31.26 0 top
NOREF#19  -  []  106.17 91.75 0 top
NOREF#20  -  []  94.47 115.6 90 top
NOREF#21  -  []  3.01 34.28 90 top
NOREF#22  -  []  101.23 81.87 0 top
NOREF#23  -  []  73.77 99.78 0 top
NOREF#24  -  []  79.52 30.82 0 top
NOREF#25  -  []  16.98 26.35 0 top
NOREF#26  -  []  94.58 20 0 top
NOREF#27  -  []  36.06 7.68 0 top
NOREF#28  -  []  -3.59 -149.37 0 top
NOREF#29  -  []  89.12 33.08 0 top
NOREF#30  -  []  49.5 63.69 0 top
NOREF#31  -  []  32.52 14.82 0 top
NOREF#32  -  []  92.68 64.07 90 top
NOREF#33  -  [unnamed#2]  110.58 14.41 0 top
NOREF#34  -  []  79.04 84.8 0 top
NOREF#35  -  []  107.21 72.89 0 top
NOREF#36  -  []  67.45 30.81 0 top
NOREF#37  -  []  21.71 63.84 90 top
NOREF#38  -  []  56.74 119.44 270 top
NOREF#39  -  [unnamed#2]  115.89 104.48 180 bottom
NOREF#40  -  [unnamed#2]  17.37 16.95 180 bottom
NOREF#41  -  []  2.38 30.67 90 bottom
NOREF#42  -  []  49.37 86.17 180 bottom
NOREF#43  -  []  88.87 91.25 180 bottom
NOREF#44  -  [unnamed#2]  100.27 14.16 180 bottom
NOREF#45  -  []  48.23 62.04 180 bottom
NOREF#46  -  []  45.08 78.65 180 bottom
NOREF#47  -  []  81.25 82.36 180 bottom
O2C53  -  [MX_C0402_SMALL_T01]  100.42 11.87 270 top
O2C54  -  [MX_C0402_SMALL_T01]  68.42 25.08 270 top
O2C56  -  [MX_C0402_SMALL_T01]  68.04 11.87 90 top
O2C59  -  [MX_C0402_SMALL_T01]  77.31 22.79 90 top
O2R1  -  [MX_R0402_SMALL_T01]  68.12 7.48 270 top
O2R132  -  [MX_R0402_SMALL_T01]  99.53 11.87 270 top
O2R240  -  [MX_R0402_SMALL_T01]  67.53 25.08 270 top
O2R241  -  [MX_R0402_SMALL_T01]  69.31 22.79 270 top
O2R242  -  [MX_R0402_SHORT_SMALL]  67.53 22.79 270 top
O2R243  -  [MX_R0402_SMALL_T01]  68.42 22.79 270 top
O2R244  -  [MX_R0402_SMALL_T01]  70.2 22.79 270 top
O2R245  -  [MX_R0402_SMALL_T01]  67.2 11.87 90 top
O2R246  -  [MX_R0402_SMALL_T01]  75.53 22.79 90 top
O2R247  -  [MX_R0402_SMALL_T01]  78.2 22.79 90 top
O2R248  -  [MX_R0402_SMALL_T01]  76.42 22.79 270 top
O2R249  -  [MX_R0402_SMALL_T01]  73.75 22.79 270 top
O2R250  -  [MX_R0402_SMALL_T01]  71.98 22.79 270 top
O2R251  -  [MX_R0402_SMALL_T01]  63.85 28.25 90 bottom
O2R252  -  [MX_R0402_SMALL_T01]  64.74 28.25 90 bottom
OP1R2  -  [MX_R0402_SMALL_T01]  10.89 53.27 0 bottom
OP1R3  -  [MX_R0402_SMALL_T01]  6.57 52.89 90 bottom
P12  -  [MX_FPC_12P_39_4HD]  82.9 10.6 90 top
P13  -  [MX_HD_2X5P_79_K4_PINREX]  117.47 92.26 90 top
P70  -  [MX_WTOB_4P_49_2H_XINA]  2.66 19.12 90 bottom
P110  -  [MX_FPC_10P_20_2H_RA_AC_H79]  6.44 23.43 270 top
PC1  -  [MX_C0402_SMALL]  60.8 93.02 90 top
PC2  -  [MX_C0805_SMALL_T02]  75.02 9.46 0 top
PC3  -  [MX_C0603_SMALL_T01]  102.96 107.55 270 top
PC4  -  [MX_C0603_SMALL_T01]  107.92 107.63 90 top
PC5  -  [MX_C0805_SMALL_T02]  111.09 100.64 0 top
PC6  -  [MX_C0603_SMALL_T01]  101.95 103.06 270 top
PC7  -  [MX_C0805_SMALL_T02]  111.73 107.88 90 top
PC8  -  [MX_C0805_SMALL_T02]  103.22 98.23 270 top
PC9  -  [MX_C0402_SMALL_T01]  103.22 95.94 270 top
PC10  -  [MX_C0603_SMALL_T01]  100.68 104.83 0 top
PC11  -  [MX_C0603_SMALL_T01]  100.68 101.28 0 top
PC12  -  [MX_C0402_SMALL_T01]  98.14 106.61 90 top
PC13  -  [MX_C0402_SMALL_T01]  98.52 99.63 90 top
PC14  -  [MX_C0603_SMALL_T01]  97.12 95.82 180 top
PC15  -  [MX_C0402_SMALL_T01]  97.17 108.77 90 top
PC16  -  [MX_C0402_SMALL_T01]  98.47 97.43 270 top
PC17  -  [MX_C0402_SMALL_T01]  96.11 106.61 90 top
PC18  -  [MX_C0603_SMALL_T01]  9.02 31.66 180 bottom
PC19  -  [MX_C1206_H75]  10.76 42.27 270 top
PC20  -  [MX_C1206_H75]  8.48 42.27 270 top
PC21  -  [MX_C1206_H75]  12.62 44 270 bottom
PC22  -  [MX_C1206_H75]  16.76 5.14 90 bottom
PC23  -  [MX_C0402_SMALL_T01]  6.44 43.75 270 top
PC24  -  [MX_C0402_SMALL_T01]  13.07 37.58 270 bottom
PC25  -  [MX_C0402_SMALL_T01]  18.2 38.92 270 top
PC26  -  [MX_C0402_SMALL]  9.11 33 0 bottom
PC27  -  [MX_C0402_SMALL_T01]  15.21 44.13 0 top
PC28  -  [MX_C0402_SMALL_T01]  13.81 46.54 90 top
PC29  -  [MX_C0805_SMALL_T02]  27.4 48.57 90 top
PC30  -  [MX_C0402_SMALL]  14.7 32.95 270 top
PC31  -  [MX_C0603_SMALL_T01]  13.56 44.61 90 top
PC32  -  [MX_C0402_SMALL_T01]  11.17 27.06 90 bottom
PC33  -  [MX_C0402_SMALL_T01]  9.11 33.84 0 bottom
PC34  -  [MX_C0402_SMALL_T01]  16.83 34.86 90 bottom
PC35  -  [MX_C0402_SMALL_T01]  17.72 35.85 270 bottom
PC36  -  [MX_C1206_H75]  19.02 6.16 90 bottom
PC37  -  [MX_C1206_H75]  21.3 6.16 90 bottom
PC38  -  [MX_C0402_SMALL_T01]  11.63 28.46 180 bottom
PC39  -  [MX_C0402_SMALL_T01]  27.83 10.27 90 bottom
PC40  -  [MX_C0603_SMALL_T01]  14.78 37.52 90 bottom
PC41  -  [MX_C0402_SMALL_T01]  25.75 4.5 0 bottom
PC42  -  [MX_C0402_SMALL_T01]  24.22 2.09 270 bottom
PC43  -  [MX_C0805_SMALL_T02]  37.74 2.6 270 bottom
PC44  -  [MX_C0603_SMALL_T01]  23.46 4 270 bottom
PC45  -  [MX_C0402_SMALL_T01]  12.06 27.06 90 bottom
PC46  -  [MX_C0402_SMALL_T01]  16.86 33.23 270 bottom
PC47  -  [MX_C0402_SMALL_T01]  19.27 32.29 180 bottom
PC48  -  [MX_C0603_SMALL]  48.61 14.16 90 bottom
PC49  -  [MX_C0603_SMALL]  47.34 14.16 90 bottom
PC50  -  [MX_C0402_SMALL_T01]  48.86 11.74 270 bottom
PC51  -  [MX_C0402_SMALL_T01]  38.19 12.12 270 bottom
PC52  -  [MX_C0603_SMALL]  38.19 14.16 90 bottom
PC53  -  [MX_C0402_SMALL_T01]  39.53 16.32 0 bottom
PC54  -  [MX_C0402_SMALL_T01]  41.5 8.57 180 bottom
PC55  -  [MX_C0402_SMALL_T01]  104.87 17.84 0 bottom
PC56  -  [MX_C0402_SMALL_T01]  94.58 16.82 90 bottom
PC57  -  [MX_C0603_SMALL]  93.95 20.38 180 bottom
PC58  -  [MX_C0402_SMALL_T01]  94.58 22.16 270 bottom
PC59  -  [MX_C0402_SMALL_T01]  94.07 18.98 0 bottom
PC60  -  [MX_C0603_SMALL]  103.85 21.4 90 bottom
PC61  -  [MX_C0603_SMALL]  105.12 21.4 90 bottom
PC62  -  [MX_C0402_SMALL_T01]  27.02 37.02 270 top
PC63  -  [MX_C0402_SMALL_T01]  22.55 48.8 90 top
PC64  -  [MX_C0402_SMALL_T01]  23.87 33.59 90 top
PC65  -  [MX_C0402_SMALL_T01]  26.51 52.13 90 top
PC66  -  [MX_C0402_SMALL_T01]  20.03 48.45 180 top
PC67  -  [MX_C0402_SMALL_T01]  20.03 29.38 90 top
PC68  -  [MX_C0402_SMALL_T01]  30.95 22.79 270 bottom
PC69  -  [MX_C0402_SMALL_T01]  27.27 17.97 90 bottom
PC70  -  [MX_C0402_SMALL_T01]  17.37 19.49 0 bottom
PC71  -  [MX_C0402_SMALL_T01]  54.7 10.73 180 bottom
PC72  -  [MX_C0402_SMALL_T01]  54.7 9.58 180 bottom
PC73  -  [MX_C0402_SMALL_T01]  52.93 6.21 0 bottom
PC74  -  [MX_C0402_SMALL_T01]  58.77 42.99 0 top
PC75  -  [MX_C0402_SMALL_T01]  54.58 36.76 270 bottom
PC76  -  [MX_C0402_SMALL_T01]  54.89 23.55 180 bottom
PC77  -  [MX_C0402_SMALL_T01]  70.2 31.91 0 bottom
PC78  -  [MX_C0402_SMALL_T01]  59.78 32.95 90 bottom
PC79  -  [MX_C0402_SMALL_T01]  62.07 30.67 180 bottom
PC80  -  [MX_C0603_SMALL]  59.53 35.11 90 bottom
PC81  -  [MX_C0402_SMALL_T01]  59.78 37.14 270 bottom
PC82  -  [MX_C0603_SMALL]  69.94 36.48 0 bottom
PC83  -  [MX_C0603_SMALL]  69.94 35.24 0 bottom
PC84  -  [MX_C0402_SMALL_T01]  39.46 18.12 180 top
PC85  -  [MX_C0603_SMALL]  32.4 19.11 90 bottom
PC86  -  [MX_C0402_SMALL_T01]  37.18 19.11 180 top
PC87  -  [MX_C0402_SMALL_T01]  37.18 20 180 top
PC88  -  [MX_C0402_SMALL_T01]  37.43 24.82 270 top
PC89  -  [MX_C0603_SMALL]  33.75 22.26 90 bottom
PC90  -  [MX_C0603_SMALL]  35.02 22.26 90 bottom
PC91  -  [MX_C0402_SMALL_T01]  39.34 21.78 0 top
PC92  -  [MX_C0402_SMALL_T01]  29.94 26.48 180 top
PC93  -  [MX_C0402_SMALL_T01]  45.18 18.09 180 bottom
PC94  -  [MX_C0402_SMALL_T01]  45.43 22.03 180 bottom
PC95  -  [MX_C0402_SMALL_T01]  42.77 20 0 top
PC96  -  [MX_C0603_SMALL]  55.72 40.08 0 top
PC97  -  [MX_C0402_SMALL_T01]  41.11 20.89 0 top
PC98  -  [MX_C0402_SMALL_T01]  41.11 21.78 0 top
PC99  -  [MX_C0402_SMALL_T01]  49.73 16.16 180 bottom
PC100  -  [MX_C0603_SMALL]  61.94 40.45 90 top
PC101  -  [MX_C0603_SMALL]  60.67 40.45 90 top
PC102  -  [MX_C0603_SMALL]  59.4 40.45 90 top
PC103  -  [MX_C0402_SMALL_T01]  42.77 19.11 180 top
PC104  -  [MX_C0603_SMALL_T01]  12.03 81.47 270 bottom
PC105  -  [MX_C1206_H75]  10.89 85.02 270 top
PC106  -  [MX_C1206_H75]  10.89 85.02 270 bottom
PC107  -  [MX_C1206_H75]  8.63 85.02 270 top
PC108  -  [MX_C1206_H75]  8.6 85.02 270 bottom
PC109  -  [MX_C0402_SMALL_T01]  5.94 86.42 180 bottom
PC110  -  [MX_C0603_SMALL_T01]  15.97 80.7 0 bottom
PC111  -  [MX_C0402_SMALL_T01]  16.48 81.59 270 top
PC112  -  [MX_C0402_SMALL_T01]  9.44 77.33 180 bottom
PC113  -  [MX_C0603_SMALL]  29.56 87.05 0 top
PC114  -  [MX_C0402_SMALL_T01]  8.86 78.16 0 bottom
PC115  -  [MX_C0603_SMALL_T01]  12.92 86.93 90 top
PC116  -  [MX_C0402_SMALL_T01]  13.02 91.12 90 top
PC117  -  [MX_C0402_SMALL_T01]  9.19 72.81 90 bottom
PC118  -  [MX_C0402_SMALL_T01]  10.86 72.81 90 bottom
PC119  -  [MX_C0603_SMALL_T01]  16.22 75.98 270 bottom
PC120  -  [MX_C0603_SMALL_T01]  15.71 72.96 0 bottom
PC121  -  [MX_C0603_SMALL_T01]  15.71 74.23 0 bottom
PC122  -  [MX_C0402_SMALL_T01]  11.69 72.81 90 bottom
PC123  -  [MX_C0402_SMALL]  105.38 59.37 180 bottom
PC124  -  [MX_C0603_SMALL_T01]  105.63 58.23 180 bottom
PC125  -  [MX_C0402_SMALL]  105.38 60.77 180 bottom
PC126  -  [MX_C0402_SMALL_T01]  65.63 10.22 90 top
PC128  -  [MX_C0402_SMALL_T01]  65.75 18.22 270 top
PC130  -  [MX_C1206_H75]  112.49 31.56 90 bottom
PC131  -  [MX_C1206_H75]  110.2 31.56 90 bottom
PC132  -  [MX_C1206_H75]  112.49 36.25 270 bottom
PC133  -  [MX_C1206_H75]  110.2 36.25 270 bottom
PC134  -  [MX_C0402_SMALL_T01]  115.16 36.25 0 bottom
PC135  -  [MX_C0402_SMALL_T01]  100.8 36.51 90 bottom
PC136  -  [MX_C0603_SMALL_T01]  107.49 55.69 90 bottom
PC137  -  [MX_C0402_SMALL]  93.82 63.41 180 bottom
PC138  -  [MX_C0402_SMALL_T01]  107.18 30.18 180 bottom
PC139  -  [MX_C0603_SMALL_T01]  107.28 31.43 0 bottom
PC140  -  [MX_C0402_SMALL_T01]  109.57 25.33 270 bottom
PC141  -  [MX_C0603_SMALL_T01]  107.28 66.61 270 bottom
PC142  -  [MX_C0402_SMALL_T01]  98.26 55.69 90 top
PC143  -  [MX_C0402_SMALL_T01]  99.15 55.69 90 top
PC144  -  [MX_C0402_SMALL_T01]  97.76 54.29 180 top
PC145  -  [MX_C0402_SMALL_T01]  95.98 58.48 0 bottom
PC146  -  [MX_C0402_SMALL_T01]  95.85 54.54 0 bottom
PC147  -  [MX_C0402_SMALL_T01]  100.04 53.27 90 bottom
PC148  -  [MX_C0402_SMALL_T01]  97.76 53.65 0 bottom
PC149  -  [MX_C0402_SMALL_T01]  100.42 56.32 0 bottom
PC150  -  [MX_C0402_SMALL_T01]  98.54 52.92 90 top
PC151  -  [MX_C0402_SMALL_T01]  100.04 55.69 270 top
PC152  -  [MX_C0402_SMALL_T01]  100.93 55.05 90 bottom
PC153  -  [MX_C0402_SMALL_T01]  98.65 56.32 0 bottom
PC154  -  [MX_C0402_SMALL_T01]  118.46 102.04 90 top
PC155  -  [MX_C0603_SMALL_T01]  105.63 62.16 180 bottom
PC156  -  [MX_C1206_H75]  115.92 92.13 90 bottom
PC157  -  [MX_C1206_H75]  111.35 92.13 90 bottom
PC158  -  [MX_C1206_H75]  113.63 92.13 90 bottom
PC159  -  [MX_C1206_H75]  109.06 92.13 90 bottom
PC160  -  [MX_C0402_SMALL_T01]  99.66 93.15 90 bottom
PC161  -  [MX_C0402_SMALL_T01]  102.33 70.42 270 bottom
PC162  -  [MX_C0402_SMALL_T01]  106.01 88.07 180 bottom
PC163  -  [MX_C0402_SMALL_T01]  100.93 70.04 0 bottom
PC164  -  [MX_C0402_SMALL_T01]  100.42 68.64 90 bottom
PC165  -  [MX_C0402_SMALL_T01]  101.82 64.19 0 bottom
PC166  -  [MX_C0402_SMALL_T01]  108.42 81.85 270 bottom
PC167  -  [MX_C0402_SMALL_T01]  101.82 65.08 0 bottom
PC168  -  [MX_C0603_SMALL_T01]  106.14 86.93 0 bottom
PC169  -  [MX_C0402_SMALL_T01]  100.42 64.7 270 bottom
PC170  -  [MX_C0402_SMALL_T01]  99.66 66.61 180 top
PC171  -  [MX_C0402_SMALL_T01]  99.66 65.72 180 top
PC172  -  [MX_C0402_SMALL_T01]  99.66 63.94 180 top
PC173  -  [MX_C0402_SMALL_T01]  101.8 66.46 0 top
PC174  -  [MX_C0402_SMALL_T01]  100.93 64.32 90 top
PC178  -  [MX_C0603_SMALL_T02]  87.24 86.42 90 top
PC179  -  [MX_C0603_SMALL_T02]  83.32 86.42 90 top
PC180  -  [MX_C0603_SMALL_T02]  84.63 86.42 90 top
PC181  -  [MX_C0603_SMALL_T02]  85.93 86.42 90 top
PC182  -  [MX_C0603_SMALL_T02]  87.24 86.42 90 bottom
PC183  -  [MX_C0603_SMALL_T02]  85.93 86.42 90 bottom
PC184  -  [MX_C0603_SMALL_T02]  84.63 86.42 90 bottom
PC185  -  [MX_C0603_SMALL_T02]  83.32 86.42 90 bottom
PC186  -  [MX_C0603_SMALL_T02]  93.16 40.45 90 top
PC187  -  [MX_C0603_SMALL_T02]  91.86 40.45 90 top
PC188  -  [MX_C0603_SMALL_T02]  72.92 35.39 180 bottom
PC189  -  [MX_C0603_SMALL_T02]  97.06 40.45 90 top
PC190  -  [MX_C0603_SMALL_T02]  98.35 40.45 90 top
PC191  -  [MX_C0603_SMALL_T02]  95.76 40.45 90 top
PC192  -  [MX_C0603_SMALL_T02]  94.46 40.45 90 top
PC193  -  [MX_C0603_SMALL_T02]  78.58 37.02 90 bottom
PC194  -  [MX_C0402_SMALL_T01]  14.72 4.33 270 top
PCB1  -  [MX_C0805_SMALL_T02]  7.84 64.07 0 bottom
PCE1  -  [MX_C7343D_H79]  40.07 72.83 270 top
PCE2  -  [MX_CESMD_260X260_H248]  31.05 43.24 270 top
PCE3  -  [MX_CESMD_260X260_H248]  32.86 14.03 0 bottom
PCE4  -  [MX_C7343D_H79]  21.57 79.42 0 top
PCE6  -  [MX_C7343D_H79]  90.39 85.02 270 top
PCE7  -  [MX_C7343D_H79]  95.47 85.02 270 top
PCE8  -  [MX_C7343D_H79]  90.39 85.02 270 bottom
PCE9  -  [MX_C7343D_H79]  96.74 38.67 270 bottom
PCE10  -  [MX_C7343D_H79]  91.79 38.67 270 bottom
PD1  -  [MX_SMA]  114.34 105.62 90 top
PD2  -  [MX_SOT323]  100.68 96.2 0 top
PD3  -  [MX_SOT323]  100.68 99.37 0 top
PJ1  -  [MX_DC_PWR_JACK_6P_LF3]  101.79 121.2 180 top
PJP1  -  [2MM_OPEN_5MIL_M1M2]  4.79 64.07 90 bottom
PJP2  -  [SHORTPIN]  104.23 104.58 180 top
PJP3  -  [SHORTPIN]  104.23 102.55 180 top
PJP4  -  [SHORTPIN]  31.05 38.67 270 top
PJP5  -  [SHORTPIN]  33.47 12 180 bottom
PJP6  -  [SHORTPIN]  33.11 21.4 0 bottom
PJP7  -  [SHORTPIN]  56.99 33.84 90 top
PJP8  -  [TV_RTC_SHORT_6X20]  23.72 79.31 180 top
PJP9  -  [SHORTPIN]  97.63 27.49 90 bottom
PJP10  -  [SHORTPIN]  97.63 30.29 270 bottom
PJP11  -  [SHORTPIN]  80.87 36.13 90 top
PJP12  -  [SHORTPIN]  78.96 37.4 180 top
PJP13  -  [SHORTPIN]  96.49 86.17 270 bottom
PJP14  -  [SHORTPIN]  96.49 83.37 90 bottom
PJP15  -  [SHORTPIN]  74.39 82.23 0 top
PJP16  -  [SHORTPIN]  74.39 80.96 180 top
PL1  -  [MX_L0805_SMALL_T02_H43]  104.61 107.5 90 top
PL2  -  [MX_L0805_SMALL_T02_H43]  106.39 107.5 90 top
PL3  -  [MX_L0805_SMALL_T02_H43]  6.44 41.46 270 top
PL4  -  [MX_L0805_SMALL_T02_H43]  16.62 3.34 0 top
PL5  -  [MX_INDUCTOR_2P_287X260]  21.68 43.37 0 top
PL6  -  [MX_INDUCTOR_2P_287X260]  32.1 5.7 0 bottom
PL7  -  [MX_L0805_SMALL_T02_H43]  5.94 85.02 0 bottom
PL8  -  [MX_L0805_SMALL_T02_H43]  5.94 83.24 0 bottom
PL9  -  [MX_INDUCTOR_2P_287X260]  21.68 85.53 0 top
PL10  -  [MX_L0805_SMALL_T02_H43]  115.16 33.08 180 bottom
PL11  -  [MX_L0805_SMALL_T02_H43]  115.16 34.86 180 bottom
PL12  -  [MX_INDUCTOR_2P_287X260]  97.63 28.89 90 bottom
PL13  -  [MX_L0805_SMALL_T02_H43]  116.78 95.61 180 bottom
PL14  -  [MX_L0805_SMALL_T02_H43]  116.78 97.39 180 bottom
PL15  -  [MX_INDUCTOR_2P_287X260]  96.49 84.77 270 bottom
PPID1  -  [LB1_LOGO_375X375]  54.15 78.85 0 top
PQ1  -  [MX_SI7900EDN]  110.46 103.95 0 top
PQ2  -  [MX_SOT23_H43]  114.77 99.25 0 top
PQ3  -  [MX_SOT23_H43]  120.05 99.64 0 top
PQ4  -  [MX_DFN_6P_26_79X79_2PAD_IR]  15.59 39.56 0 top
PQ5  -  [MX_DFN_6P_26_79X79_2PAD_IR]  15.59 46.03 180 top
PQ6  -  [MX_DFN_6P_26_79X79_2PAD_IR]  26 8.95 0 bottom
PQ7  -  [MX_DFN_6P_26_79X79_2PAD_IR]  26 2.6 180 bottom
PQ8  -  [MX_SOT23_2D4_H44]  24.73 37.52 0 top
PQ9  -  [MX_SOT23_2D4_H44]  24.73 49.21 180 top
PQ10  -  [MX_SOT323_S5]  20.15 50.35 270 top
PQ11  -  [MX_SOT323_S5]  20.92 32.32 0 top
PQ12  -  [MX_SOT23_H43]  20.33 53.65 180 top
PQ13  -  [MX_SOT23_H43]  21.3 37.52 270 top
PQ14  -  [MX_DFN_6P_26_79X79_2PAD_IR]  30.32 19.24 90 bottom
PQ15  -  [MX_SOT323_S5]  21.94 19.59 90 bottom
PQ16  -  [MX_SOT23_H43]  22.06 16.32 180 bottom
PQ17  -  [MX_SOT23_2D4_H44]  51.66 11.74 270 bottom
PQ18  -  [MX_SOT323_S5]  49.69 5.27 270 bottom
PQ19  -  [MX_SOT23_H43]  49.62 8.31 180 bottom
PQ20  -  [MX_SOT23_2D4_H44]  55.97 40.45 270 bottom
PQ21  -  [MX_SOT323_S5]  52.29 25.08 180 bottom
PQ22  -  [MX_SOT23_H43]  52.42 31.81 270 bottom
PQ23  -  [MX_DFN_6P_26_79X79_2PAD_IR]  34.51 19.24 90 bottom
PQ24  -  [MX_SOT23_H43]  33.96 24.44 180 top
PQ25  -  [MX_SOT23_H43]  29.62 24.44 180 top
PQ26  -  [MX_SO_8FL_COLAY]  54.45 36.38 90 top
PQ27  -  [MX_SOT23_H43]  48.95 18.73 270 bottom
PQ28  -  [MX_SOT23_H43]  52.14 18.47 270 bottom
PQ29  -  [MX_DFN_6P_26_79X79_2PAD_IR]  13.81 81.97 0 top
PQ30  -  [MX_DFN_6P_26_79X79_2PAD_IR]  15.21 90.61 180 top
PQ31  -  [MX_SO_8FL_COLAY]  105.25 35.24 90 bottom
PQ32  -  [MX_SOT23_H43]  103.29 52.33 270 bottom
PQ33  -  [MX_SOT23_H43]  63.34 15.17 270 top
PQ35  -  [MX_SOT23_H43]  69.94 15.17 270 top
PQ36  -  [MX_SOT23]  63.34 10.85 270 top
PQ38  -  [MX_SOT23]  66.64 15.17 270 top
PQ41  -  [MX_SOT23_H61]  106.49 52.33 270 bottom
PQ42  -  [MX_SO_8FL_COLAY]  105.12 26.6 270 bottom
PQ43  -  [MX_SOT23_H43]  104.36 69.91 90 bottom
PQ44  -  [MX_SOT23_H61]  107.66 69.91 90 bottom
PQ45  -  [MX_SO_8FL_COLAY]  104.11 91.75 90 bottom
PQ46  -  [MX_SO_8FL_COLAY]  103.98 83.12 270 bottom
PQ47  -  [MX_DFN_6P_26_79X79_2PAD_IR]  15.21 87.44 180 top
PR1  -  [MX_R0402_SMALL_T01]  84.17 40.57 90 bottom
PR2  -  [MX_R0402_SMALL_T01]  70.2 61.15 90 top
PR3  -  [MX_R0402_SMALL_T01]  70.2 62.92 270 top
PR4  -  [MX_R1508]  106.27 103.56 270 top
PR5  -  [MX_R0603_SMALL_T01]  109.69 106.94 0 top
PR6  -  [MX_R0603_SMALL_T01]  109.72 108.16 0 top
PR7  -  [MX_R0603_SMALL_T01]  109.72 109.38 0 top
PR8  -  [MX_R0603_SMALL_T01]  109.34 110.6 0 top
PR9  -  [MX_R0402_SMALL_T01]  111.6 97.6 0 top
PR10  -  [MX_R0402_SMALL_T01]  111.6 98.48 0 top
PR11  -  [MX_R0402_SMALL_T01]  111.6 99.37 0 top
PR12  -  [MX_R0402_SMALL_T01]  100.42 103.56 0 top
PR13  -  [MX_R0402_SMALL_T01]  100.42 102.55 0 top
PR14  -  [MX_R0402_SMALL_T01]  117.44 99.75 270 top
PR15  -  [MX_R0402_SMALL_T01]  97.63 97.43 90 top
PR16  -  [MX_R0402_SMALL_T01]  96.79 97.43 90 top
PR17  -  [MX_R0402_SMALL_T01]  96.28 108.77 270 top
PR18  -  [MX_R0603_SMALL_T01]  99.28 106.87 270 top
PR19  -  [MX_R0402_SMALL_T01]  95.57 95.82 270 top
PR20  -  [MX_R0402_SMALL_T01]  95.95 97.43 90 top
PR21  -  [MX_R0402_SMALL_T01]  97.5 99.63 90 top
PR22  -  [MX_R0402_SMALL_T01]  97.12 106.61 90 top
PR23  -  [MX_R0402_SMALL_T01]  95.27 108.77 270 top
PR24  -  [MX_R0402_SMALL_T01]  95.47 99.63 270 top
PR25  -  [MX_R0402_SMALL_T01]  96.49 99.63 270 top
PR26  -  [MX_R0402_SMALL_T01]  95.22 106.61 270 top
PR27  -  [MX_R1206_H26]  6.24 29.9 0 bottom
PR28  -  [MX_R0805_SMALL_T02]  11.78 37.14 90 bottom
PR30  -  [MX_R0402_SMALL_T01]  17.37 38.92 270 top
PR32  -  [MX_R1206]  14.34 42.22 180 top
PR33  -  [MX_R0402_SMALL_T01]  12.92 46.54 90 top
PR34  -  [MX_R0402_SMALL_T01]  10.41 25.46 90 bottom
PR35  -  [MX_R0603_SMALL_T01]  9.36 35.49 270 bottom
PR36  -  [MX_R0402_SMALL_T01]  16.5 36.07 0 bottom
PR37  -  [MX_R0402_SMALL_T01]  17.75 34.12 180 top
PR38  -  [MX_R0402_SMALL_T01]  15.99 34.86 270 bottom
PR39  -  [MX_R0402_SMALL_T01]  17.21 32.01 0 bottom
PR40  -  [MX_R0805_SMALL_T02]  10.36 29.75 180 bottom
PR41  -  [MX_R0402_SMALL_T01]  15.79 37.27 270 bottom
PR43  -  [MX_R0402_SMALL_T01]  28.72 10.27 270 bottom
PR44  -  [MX_R0402_SHORT_SMALL]  16.63 37.27 270 bottom
PR46  -  [MX_R1206]  24.86 6.28 180 bottom
PR47  -  [MX_R0402_SMALL_T01]  11.42 25.46 90 bottom
PR48  -  [MX_R0402_SMALL_T01]  23.33 2.09 90 bottom
PR49  -  [MX_R0402_SMALL_T01]  17.75 33.23 90 bottom
PR50  -  [MX_R0402_SMALL_T01]  19.27 33.13 180 bottom
PR51  -  [MX_R0603_SMALL_T01]  42 16.32 180 bottom
PR52  -  [MX_R0402_SMALL_T01]  38.19 10.47 270 bottom
PR53  -  [MX_R0402_SMALL_T01]  47.97 11.74 90 bottom
PR54  -  [MX_R0402_SMALL_T01]  48.48 10.47 0 bottom
PR56  -  [MX_R0402_SMALL_T01]  47.11 11.74 270 bottom
PR57  -  [MX_R0402_SMALL_T01]  39.62 8.57 0 bottom
PR59  -  [MX_R0402_SMALL_T01]  93.57 16.82 90 bottom
PR60  -  [MX_R0603_SMALL_T01]  93.44 22.41 270 bottom
PR61  -  [MX_R0402_SMALL_T01]  94.07 18.09 180 bottom
PR62  -  [MX_R0402_SMALL_T01]  104.87 18.86 180 bottom
PR63  -  [MX_R0402_SMALL_T01]  104.87 19.74 0 bottom
PR65  -  [MX_R0402_SMALL_T01]  103.6 18.47 270 bottom
PR67  -  [MX_R0402_SMALL_T01]  23.46 34.86 0 top
PR68  -  [MX_R0402_SMALL_T01]  22.95 33.59 90 top
PR69  -  [MX_R0402_SMALL_T01]  25.49 52.13 270 top
PR70  -  [MX_R0402_SMALL_T01]  26 53.53 0 top
PR71  -  [MX_R0402_SMALL_T01]  24.22 53.53 0 top
PR72  -  [MX_R0402_SMALL_T01]  22.95 31.81 90 top
PR73  -  [MX_R0402_SHORT_SMALL]  24.22 54.42 180 top
PR74  -  [MX_R0402_SMALL_T01]  17.62 50.1 90 top
PR75  -  [MX_R0402_SHORT_SMALL]  21.68 34.81 180 top
PR76  -  [MX_R0402_SMALL_T01]  21.3 29.78 180 top
PR77  -  [MX_R0402_SMALL_T01]  18.38 48.45 0 top
PR78  -  [MX_R0402_SMALL_T01]  26 54.42 0 top
PR79  -  [MX_R0402_SMALL_T01]  23.97 31.81 270 top
PR80  -  [MX_R0402_SMALL_T01]  19.14 29.38 90 top
PR81  -  [MX_R0402_SMALL_T01]  26.76 19.64 0 bottom
PR82  -  [MX_R0402_SMALL_T01]  26.38 17.97 270 bottom
PR83  -  [MX_R0402_SMALL_T01]  25.11 17.2 0 bottom
PR84  -  [MX_R0402_SHORT_SMALL]  24.66 15.81 270 bottom
PR85  -  [MX_R0402_SMALL_T01]  19.02 20.38 180 bottom
PR86  -  [MX_R0402_SMALL_T01]  19.02 19.49 0 bottom
PR87  -  [MX_R0402_SMALL_T01]  17.37 21.78 180 bottom
PR88  -  [MX_R0402_SMALL_T01]  25.49 15.81 270 bottom
PR90  -  [MX_R0402_SMALL_T01]  19.02 21.78 180 bottom
PR91  -  [MX_R0402_SMALL_T01]  52.93 8.82 180 bottom
PR92  -  [MX_R0402_SMALL_T01]  54.2 8.31 270 bottom
PR93  -  [MX_R0402_SMALL_T01]  52.93 7.04 0 bottom
PR94  -  [MX_R0402_SHORT_SMALL]  52.93 7.93 180 bottom
PR95  -  [MX_R0402_SMALL_T01]  52.93 5.37 180 bottom
PR96  -  [MX_R0402_SMALL_T01]  54.7 7.04 0 bottom
PR97  -  [MX_R0402_SMALL_T01]  55.21 8.31 90 bottom
PR98  -  [MX_R0402_SMALL_T01]  54.7 6.21 180 bottom
PR99  -  [MX_R0402_SMALL_T01]  54.7 5.37 180 bottom
PR100  -  [MX_R0402_SMALL_T01]  55.47 36.76 90 bottom
PR101  -  [MX_R0402_SMALL_T01]  54.2 35.37 0 bottom
PR102  -  [MX_R0402_SMALL_T01]  52.57 34.48 0 bottom
PR103  -  [MX_R0402_SHORT_SMALL]  54.2 34.48 0 bottom
PR104  -  [MX_R0402_SMALL_T01]  54.5 24.82 90 bottom
PR105  -  [MX_R0402_SMALL_T01]  52.57 35.37 180 bottom
PR106  -  [MX_R0402_SMALL_T01]  54.89 22.67 180 bottom
PR107  -  [MX_R0402_SMALL_T01]  55.34 24.82 270 bottom
PR108  -  [MX_R0402_SMALL_T01]  54.89 21.78 180 bottom
PR109  -  [MX_R0402_SMALL_T01]  62.07 29.78 180 bottom
PR110  -  [MX_R0402_SMALL_T01]  58.89 32.95 90 bottom
PR111  -  [MX_R0603_SMALL_T01]  57.52 36.43 270 bottom
PR112  -  [MX_R0402_SMALL_T01]  70.2 32.93 0 bottom
PR113  -  [MX_R0402_SMALL_T01]  69.64 34.2 0 bottom
PR115  -  [MX_R0402_SMALL_T01]  68.93 32.7 270 bottom
PR117  -  [MX_R0402_SMALL_T01]  39.46 18.96 0 top
PR118  -  [MX_R0402_SMALL_T01]  35.02 19.11 180 top
PR119  -  [MX_R0402_SMALL_T01]  33.75 19.49 270 top
PR120  -  [MX_R0402_SMALL_T01]  38.32 24.82 90 top
PR121  -  [MX_R0402_SMALL_T01]  32.61 19.49 90 top
PR122  -  [MX_R0402_SMALL_T01]  36.54 24.82 270 top
PR123  -  [MX_R0402_SMALL_T01]  35.02 20.63 180 top
PR124  -  [MX_R0402_SMALL_T01]  37.18 20.89 180 top
PR125  -  [MX_R0402_SMALL_T01]  35.02 21.52 180 top
PR126  -  [MX_R0402_SMALL_T01]  28.29 26.48 0 top
PR127  -  [MX_R0402_SMALL_T01]  37.18 21.78 180 top
PR129  -  [MX_R0402_SMALL_T01]  39.34 20.95 0 top
PR131  -  [MX_R0402_SMALL_T01]  26.51 24.95 90 top
PR132  -  [MX_R0402_SMALL_T01]  45.01 23.25 90 bottom
PR133  -  [MX_R0402_SMALL_T01]  45.43 21.14 180 bottom
PR134  -  [MX_R0402_SMALL_T01]  41.11 20 0 top
PR135  -  [MX_R0402_SMALL_T01]  42.38 21.4 90 top
PR136  -  [MX_R0402_SMALL_T01]  43.27 21.4 270 top
PR137  -  [MX_R0402_SMALL_T01]  48.07 16.16 0 bottom
PR138  -  [MX_R0402_SMALL_T01]  45.2 20.28 0 bottom
PR139  -  [MX_R0402_SMALL_T01]  54.83 19.74 180 bottom
PR140  -  [MX_R0402_SMALL_T01]  42.77 22.67 0 top
PR141  -  [MX_R0402_SMALL_T01]  54.83 18.86 180 bottom
PR142  -  [MX_R0402_SMALL_T01]  41.11 22.67 0 top
PR143  -  [MX_R0402_SMALL_T01]  42.77 18.22 0 top
PR144  -  [MX_R0402_SMALL_T01]  41.11 18.22 0 top
PR145  -  [MX_R0402_SMALL_T01]  41.11 19.11 0 top
PR146  -  [MX_R0603_SMALL_T01]  10.76 81.47 270 bottom
PR147  -  [MX_R0805_SMALL_T02]  16.22 78.55 90 bottom
PR148  -  [MX_R0402_SMALL_T01]  8.63 79.18 0 bottom
PR149  -  [MX_R0402_SMALL_T01]  5.63 78.44 0 bottom
PR151  -  [MX_R0402_SMALL_T01]  5.63 79.28 0 bottom
PR152  -  [MX_R0402_SMALL_T01]  15.59 81.59 90 top
PR153  -  [MX_R1206]  14.44 84.64 180 top
PR154  -  [MX_R0402_SMALL_T01]  5.63 80.12 0 bottom
PR156  -  [MX_R0402_SMALL_T01]  12.13 91.12 270 top
PR157  -  [MX_R0402_SMALL_T01]  8.63 80.07 0 bottom
PR158  -  [MX_R0402_SMALL_T01]  10.03 72.81 90 bottom
PR159  -  [MX_R0402_SMALL_T01]  9.82 75.96 270 bottom
PR160  -  [MX_R0402_SMALL_T01]  13.17 81.21 90 bottom
PR164  -  [MX_R0402_SMALL_T01]  12.51 72.81 90 bottom
PR165  -  [MX_R0402_SHORT_SMALL]  107.79 59.37 180 bottom
PR166  -  [MX_R0805_SMALL_T02]  103.98 56.57 0 bottom
PR168  -  [MX_R0402_SMALL_T01]  69.94 18.22 270 top
PR169  -  [MX_R0402_SMALL_T01]  62.45 18.22 270 top
PR170  -  [MX_R0402_SMALL_T01]  65.63 11.87 270 top
PR172  -  [MX_R0402_SMALL_T01]  66.64 18.22 270 top
PR173  -  [MX_R0402_SMALL_T01]  66.51 10.22 270 top
PR175  -  [MX_R0402_SMALL_T01]  64.86 18.22 90 top
PR177  -  [MX_R0402_SMALL_T01]  63.34 18.22 90 top
PR178  -  [MX_R0402_SMALL_T01]  69.05 18.22 90 top
PR181  -  [MX_R0603_SMALL_T01]  108.04 60.77 180 bottom
PR182  -  [MX_R0402_SMALL_T01]  106.14 55.43 270 bottom
PR183  -  [MX_R0402_SMALL_T01]  104.87 55.05 180 bottom
PR184  -  [MX_R0402_SHORT_SMALL]  103.22 55.05 180 bottom
PR186  -  [MX_R0402_SMALL_T01]  108.04 57.69 270 bottom
PR187  -  [MX_R0402_SMALL_T01]  104.51 66.86 90 bottom
PR188  -  [MX_R0402_SMALL_T01]  99.92 36.51 270 bottom
PR189  -  [MX_R0402_SMALL_T01]  103.34 64.7 90 bottom
PR190  -  [MX_R0402_SMALL_T01]  101.77 55.27 270 bottom
PR191  -  [MX_R1206]  103.73 30.92 0 bottom
PR192  -  [MX_R0402_SMALL_T01]  93.82 62.54 0 bottom
PR193  -  [MX_R0402_SMALL_T01]  93.82 61.65 0 bottom
PR194  -  [MX_R0402_SMALL_T01]  93.82 60.82 0 bottom
PR195  -  [MX_R0402_SMALL_T01]  93.82 59.98 0 bottom
PR196  -  [MX_R0402_SMALL_T01]  106.14 66.86 90 bottom
PR198  -  [MX_R0603_SMALL_T01]  95.98 59.62 0 bottom
PR199  -  [MX_R0402_SMALL_T01]  110.58 25.33 90 bottom
PR200  -  [MX_R0402_SHORT_SMALL]  95.98 60.77 0 bottom
PR201  -  [MX_R0402_SMALL_T01]  108.35 66.86 90 bottom
PR202  -  [MX_R0402_SMALL_T01]  95.98 61.65 0 bottom
PR203  -  [MX_R0402_SMALL_T01]  96.36 52.89 90 top
PR204  -  [MX_R0402_SMALL_T01]  93.82 58.48 0 bottom
PR205  -  [MX_R0402_SMALL_T01]  97.25 55.69 270 top
PR206  -  [MX_R0402_SMALL_T01]  93.41 29.14 90 bottom
PR207  -  [MX_R0402_SMALL_T01]  97.25 52.89 270 top
PR208  -  [MX_R0402_SMALL_T01]  97.76 55.43 180 bottom
PR209  -  [MX_R0402_SMALL_T01]  100.93 53.27 270 bottom
PR210  -  [MX_R0402_SMALL_T01]  99.81 53.43 0 top
PR211  -  [MX_R0402_SMALL_T01]  97.76 54.54 0 bottom
PR212  -  [MX_R0402_SMALL_T01]  99.53 54.29 0 top
PR213  -  [MX_R0402_SMALL_T01]  99.03 55.05 90 bottom
PR214  -  [MX_R0402_SMALL_T01]  99.92 55.05 90 bottom
PR215  -  [MX_R0402_SHORT_SMALL]  97.76 52.76 0 bottom
PR216  -  [MX_R0402_SMALL_T01]  99.81 52.54 0 top
PR217  -  [MX_R0402_SMALL_T01]  99.03 53.27 90 bottom
PR218  -  [MX_R0805_SMALL_T02]  106.01 63.69 0 bottom
PR219  -  [MX_R0402_SMALL_T01]  95.85 55.43 180 bottom
PR221  -  [MX_R0402_SMALL_T01]  95.85 56.32 180 bottom
PR222  -  [MX_R0402_SMALL_T01]  95.98 57.46 180 bottom
PR223  -  [MX_R0402_SMALL_T01]  98.77 93.15 270 bottom
PR224  -  [MX_R0402_SMALL_T01]  93.82 57.46 0 bottom
PR225  -  [MX_R0402_SMALL_T01]  102.33 68.64 90 bottom
PR226  -  [MX_R0402_SMALL_T01]  102.33 66.48 90 bottom
PR228  -  [MX_R1206]  102.58 87.44 0 bottom
PR229  -  [MX_R0402_SMALL_T01]  100.42 66.48 90 bottom
PR230  -  [MX_R0402_SMALL_T01]  109.31 81.85 90 bottom
PR231  -  [MX_R0402_SMALL_T01]  101.44 68.64 270 bottom
PR232  -  [MX_R0402_SMALL_T01]  101.44 66.48 90 bottom
PR233  -  [MX_R0402_SHORT_SMALL]  95.88 63.05 180 bottom
PR234  -  [MX_R0402_SHORT_SMALL]  100.93 70.93 0 bottom
PR235  -  [MX_R0402_SMALL_T01]  100.93 71.81 0 bottom
